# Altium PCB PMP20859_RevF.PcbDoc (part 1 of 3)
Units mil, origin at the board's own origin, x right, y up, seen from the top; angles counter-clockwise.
Board outline 5000 x 4200 mil, 4 copper layers (Top Layer, Signal Layer 1, Signal Layer 2, Bottom Layer), stack 61.2 mil thick; 264 components, 163 nets, 897 pads, 223 vias.
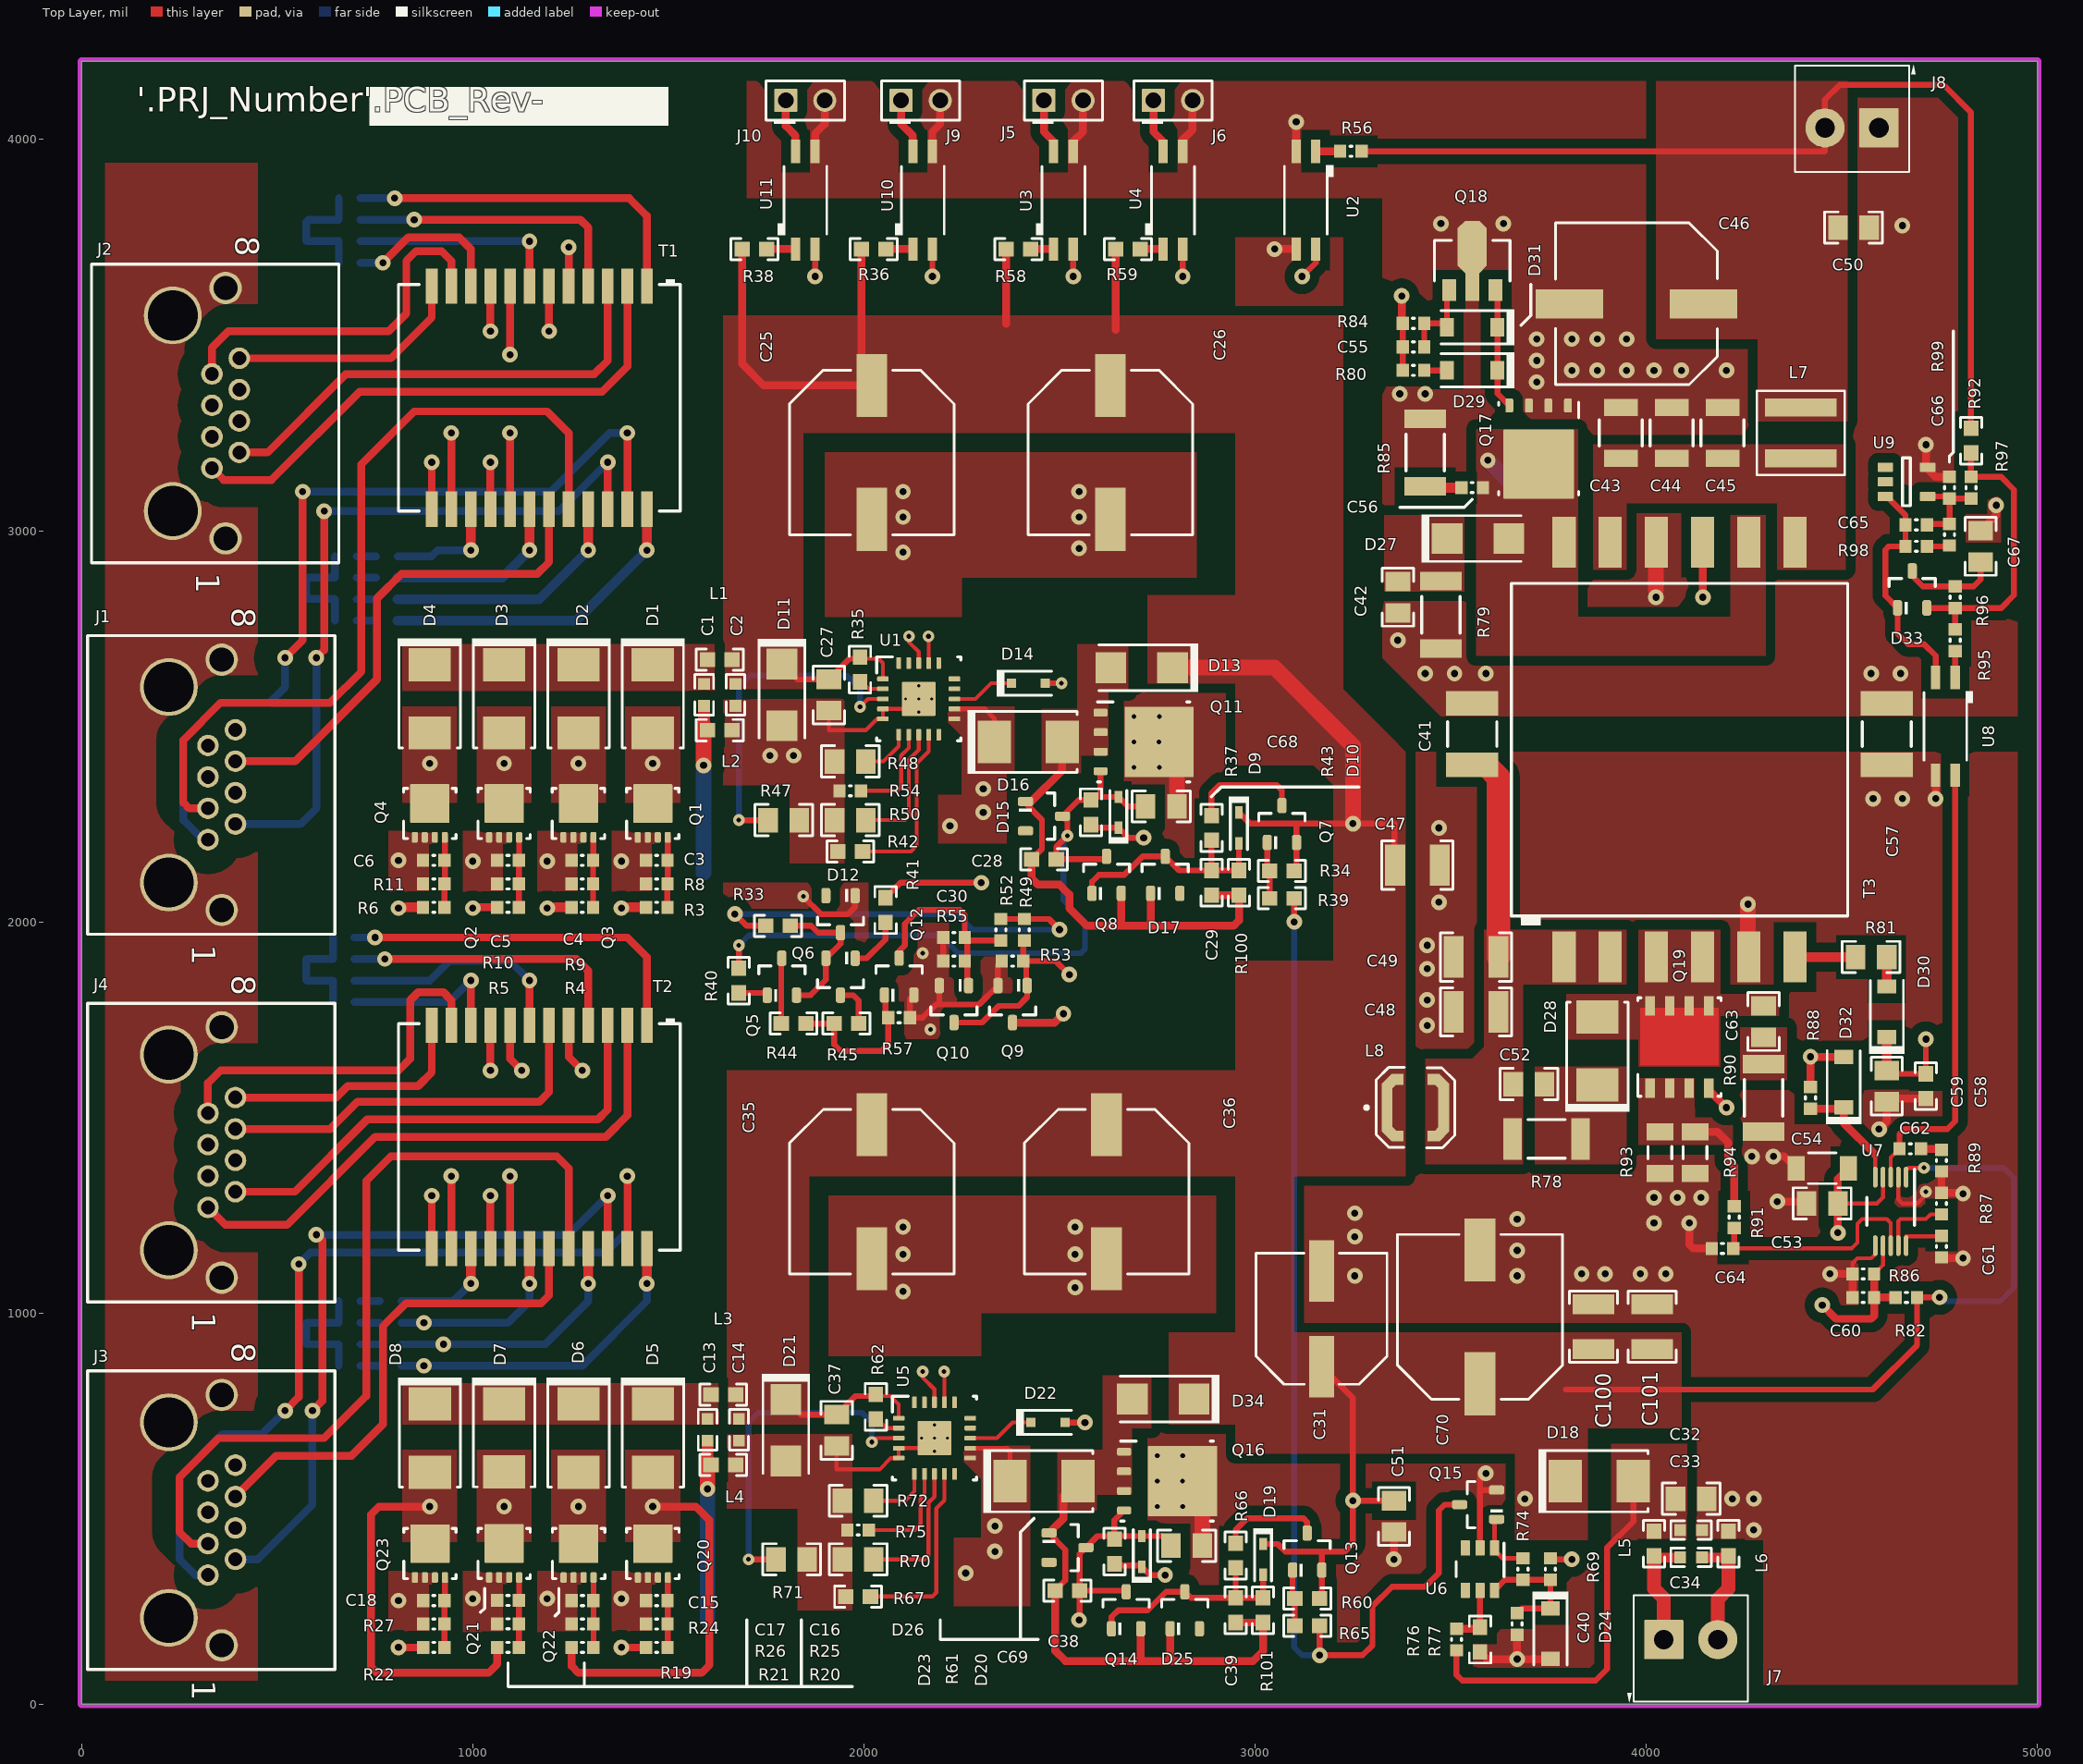
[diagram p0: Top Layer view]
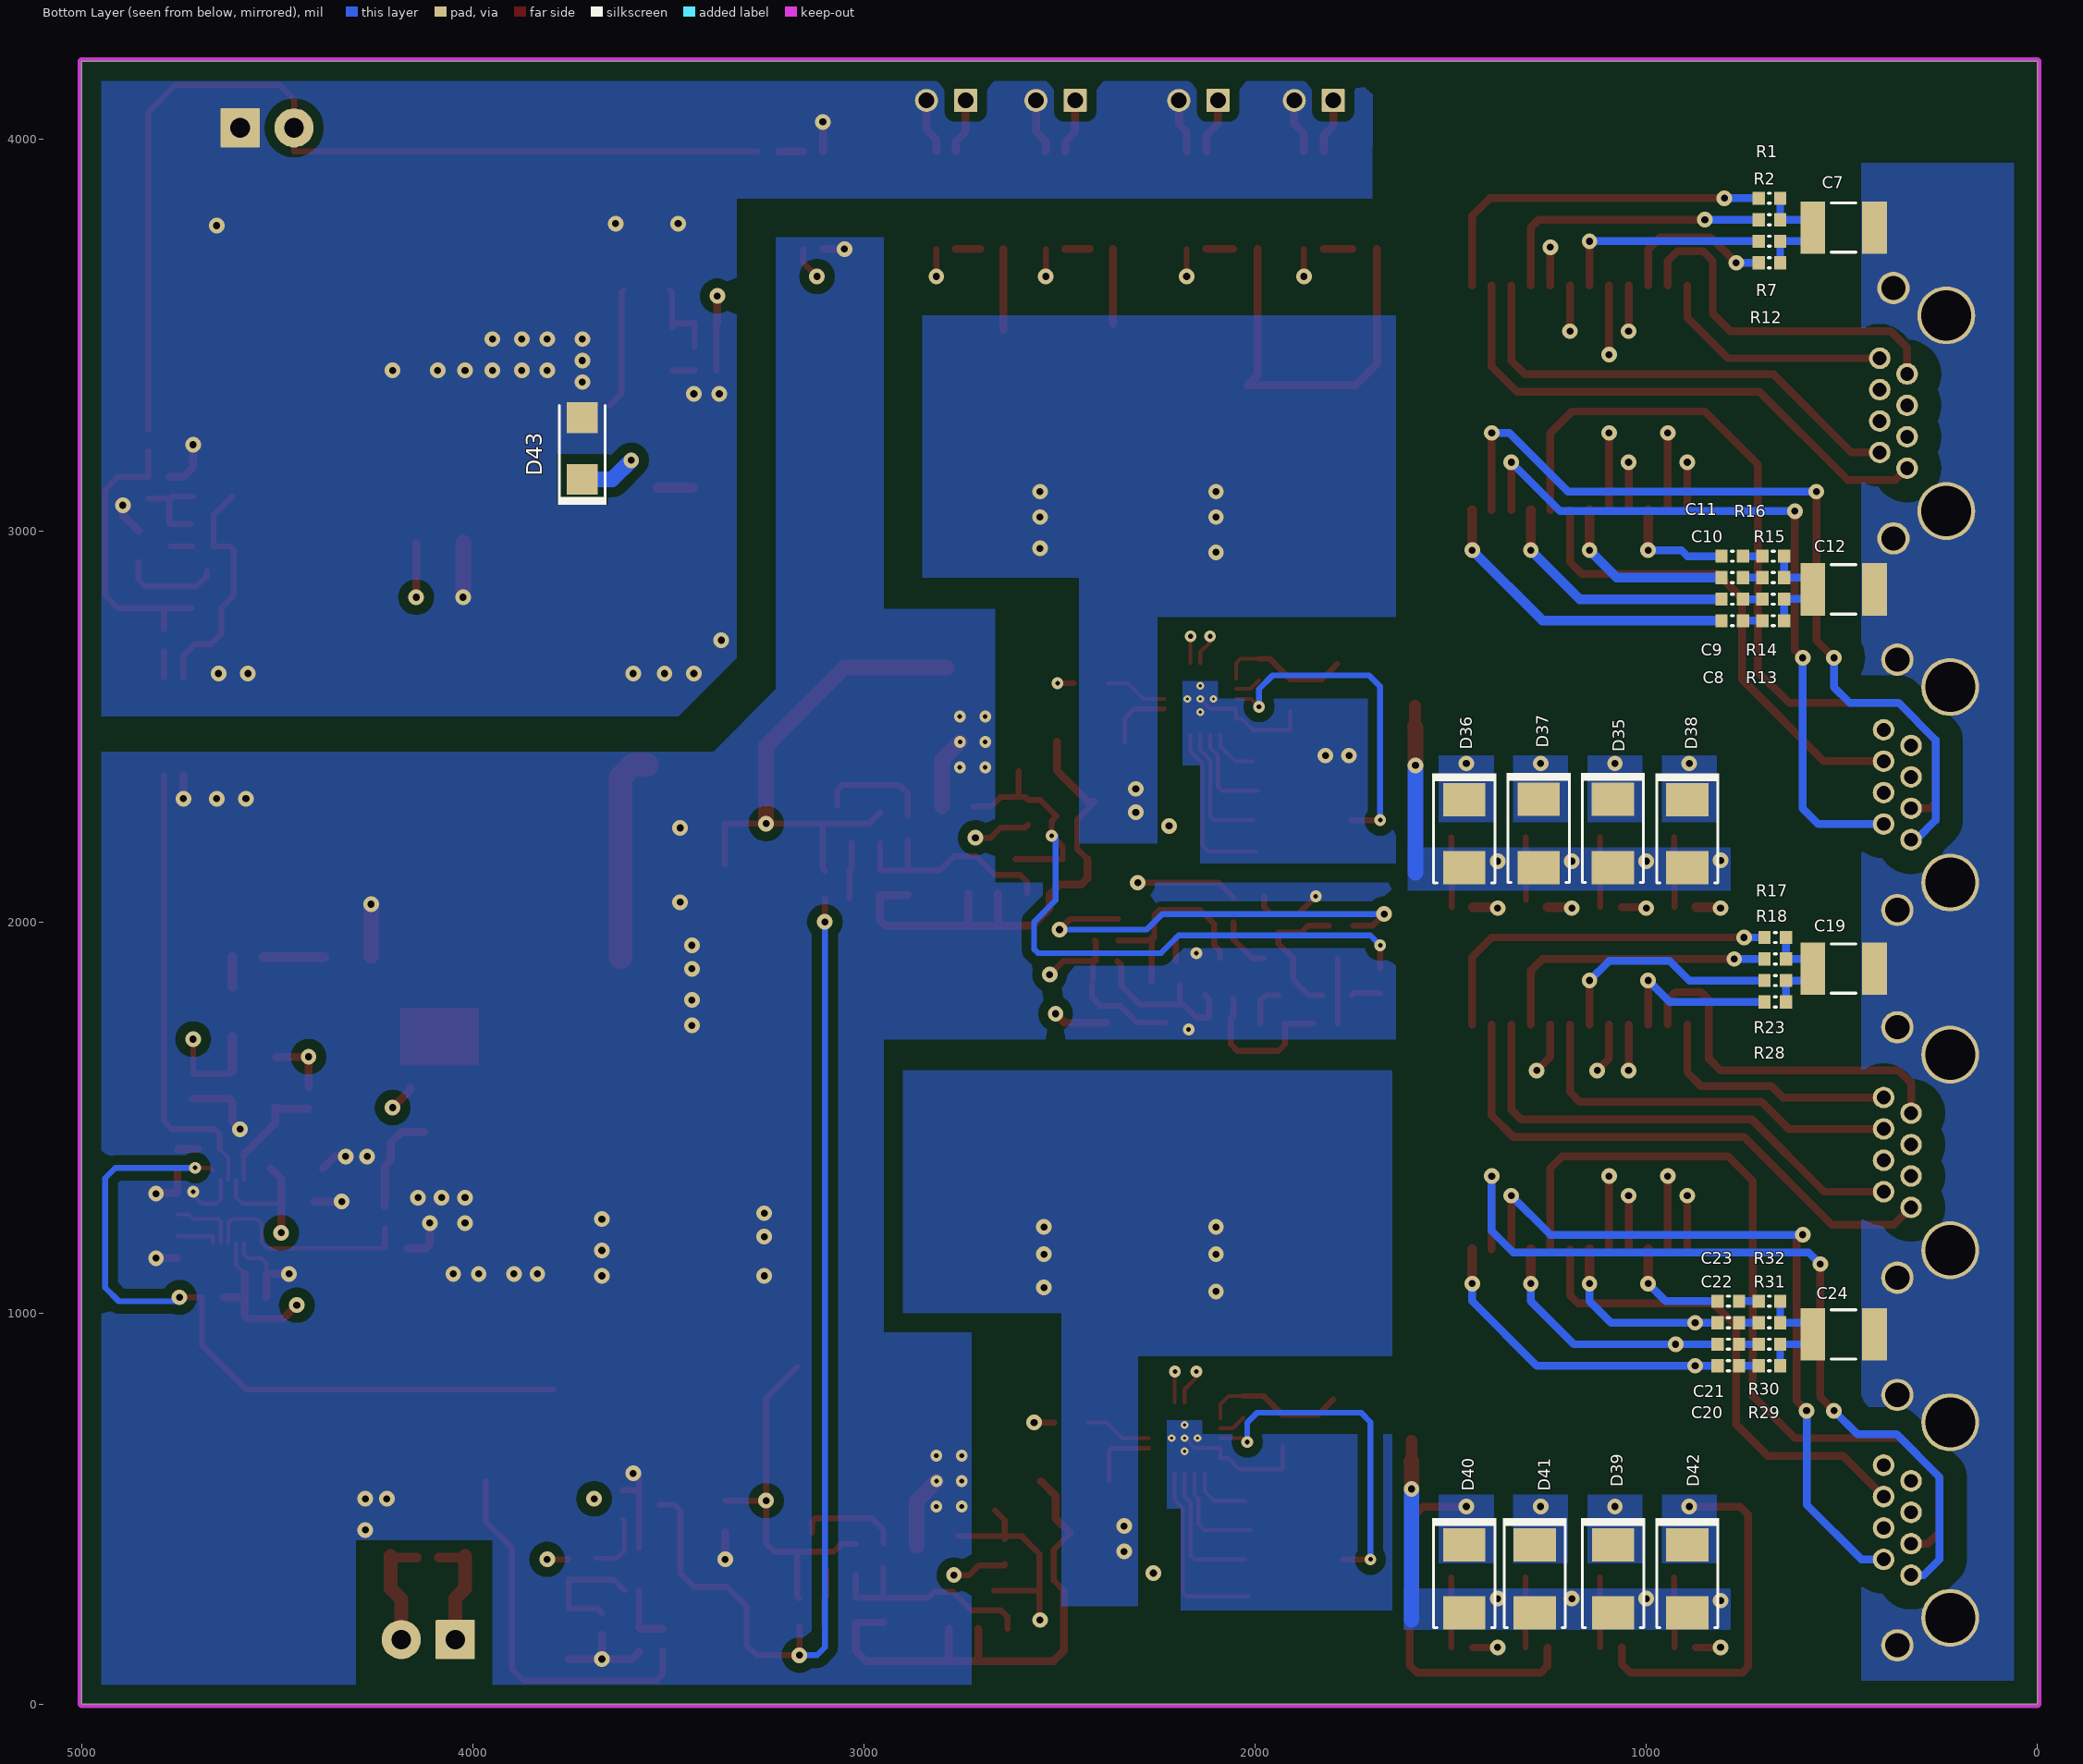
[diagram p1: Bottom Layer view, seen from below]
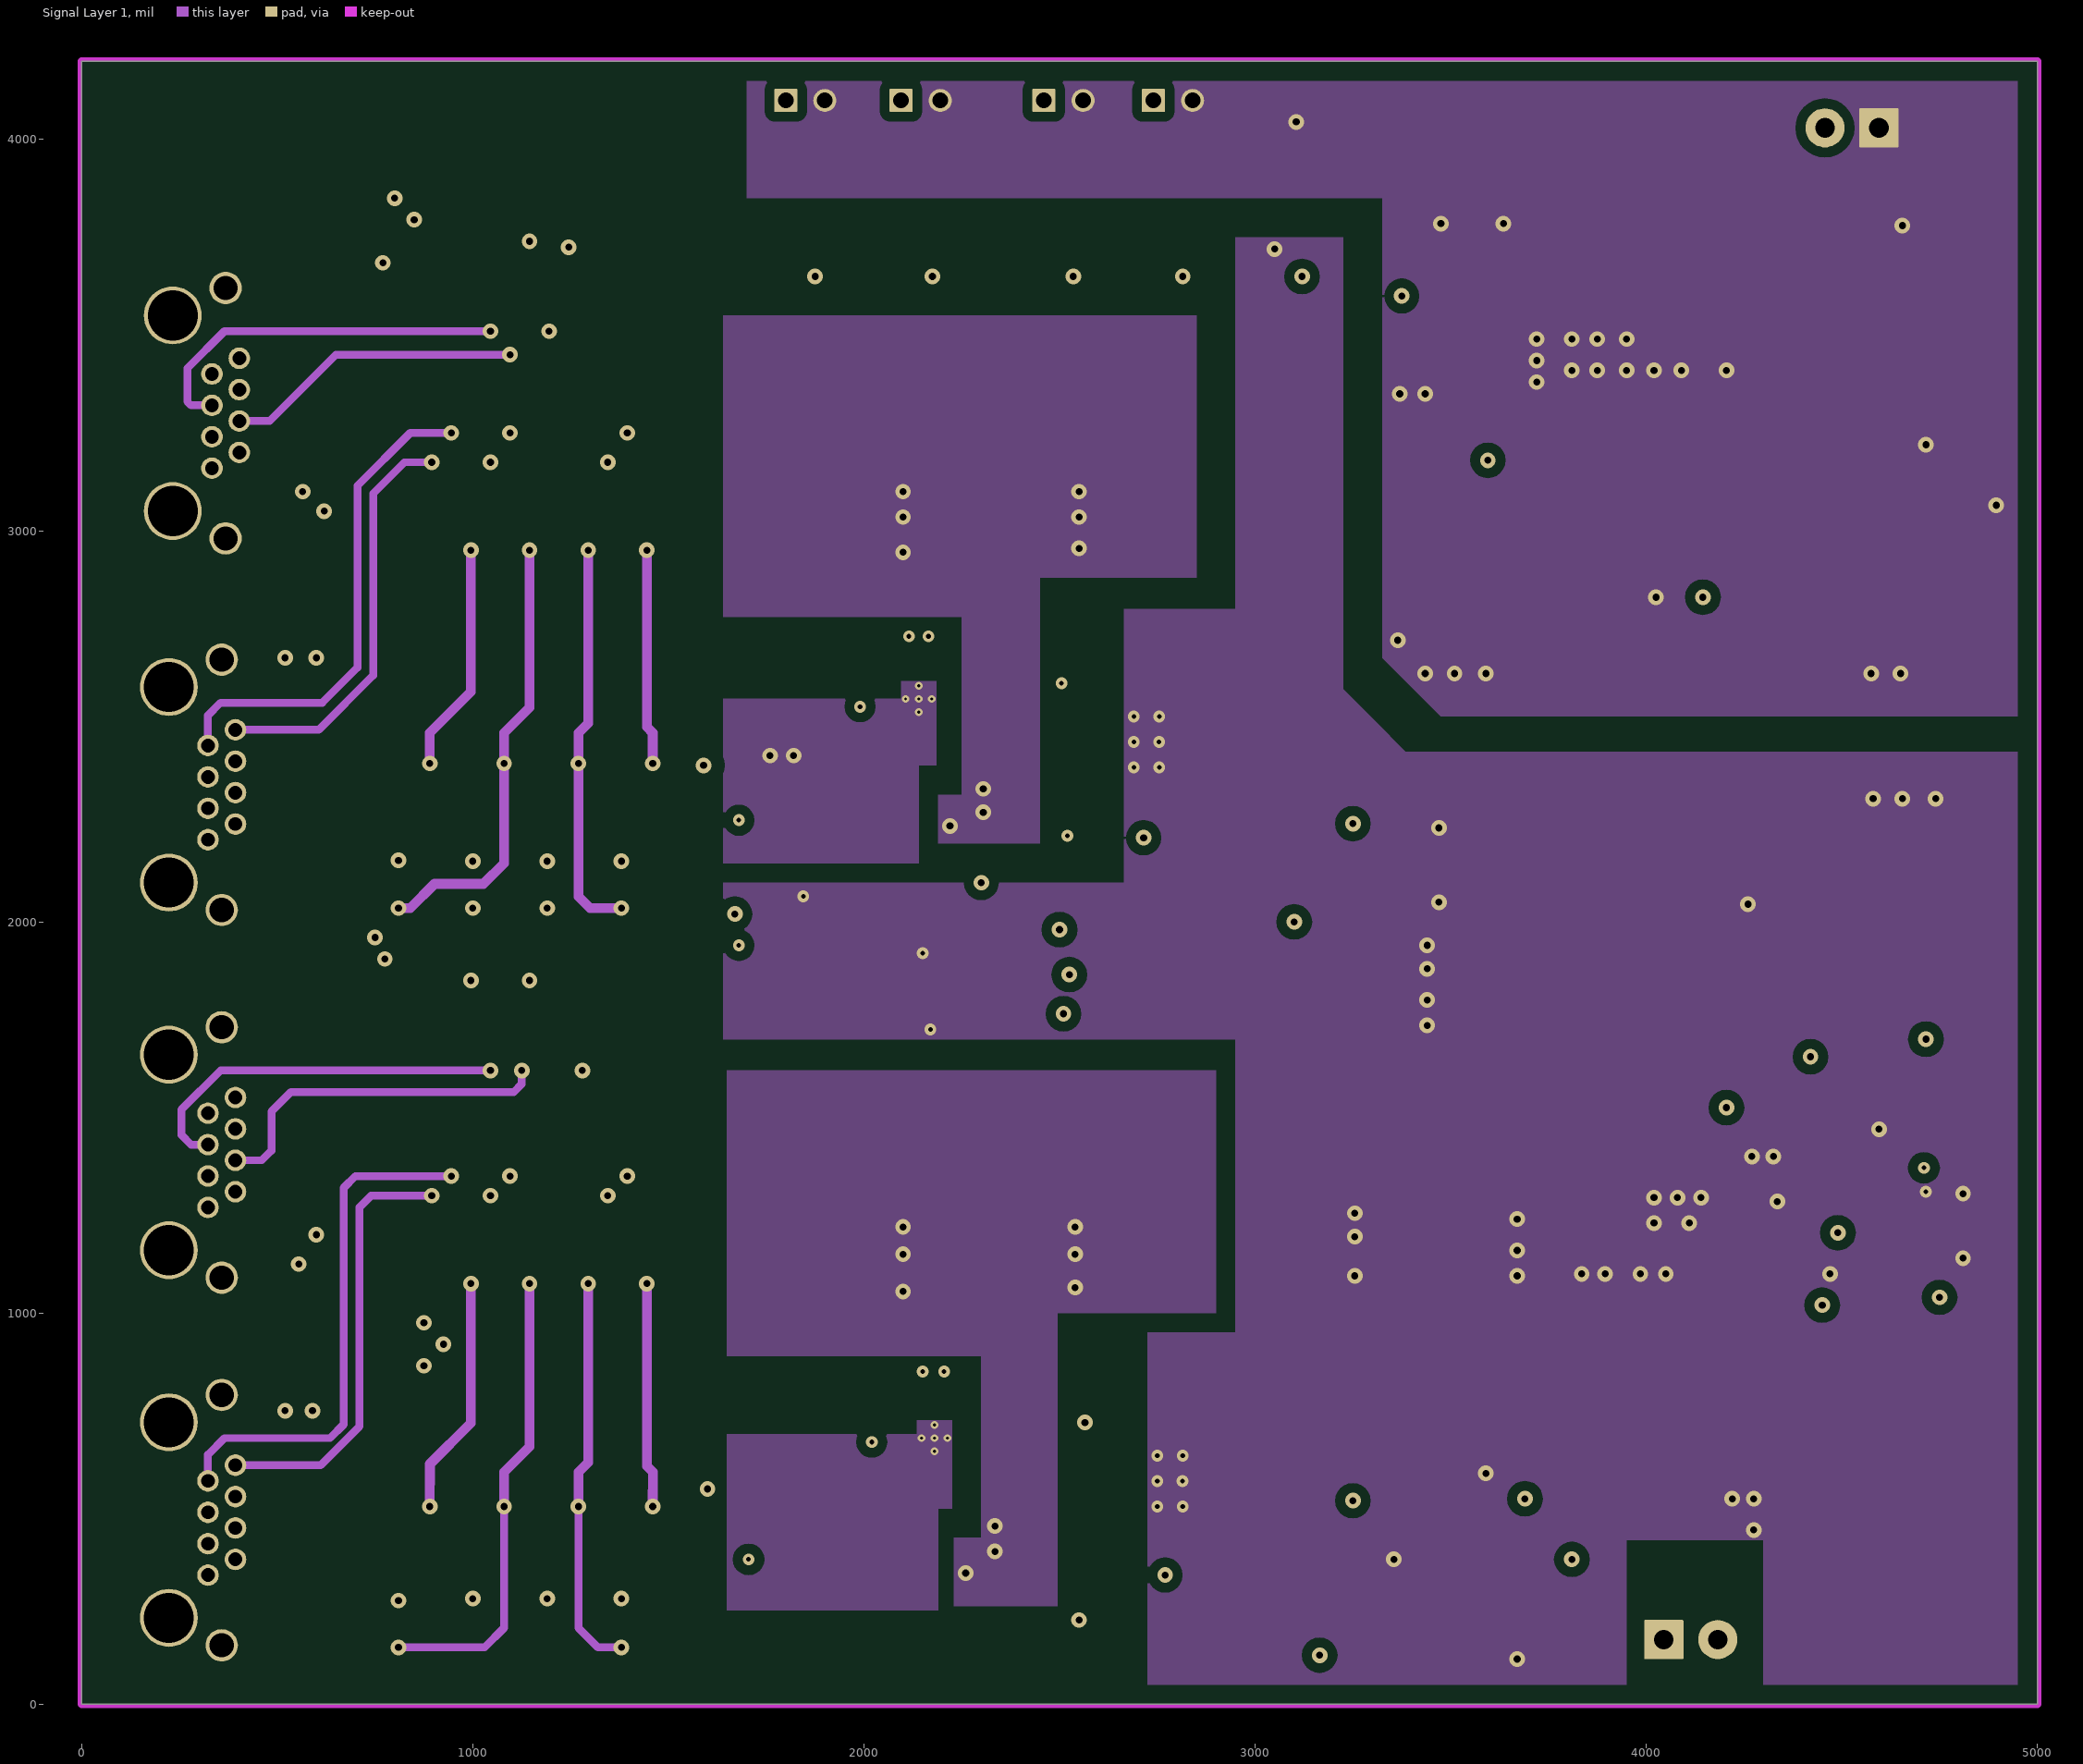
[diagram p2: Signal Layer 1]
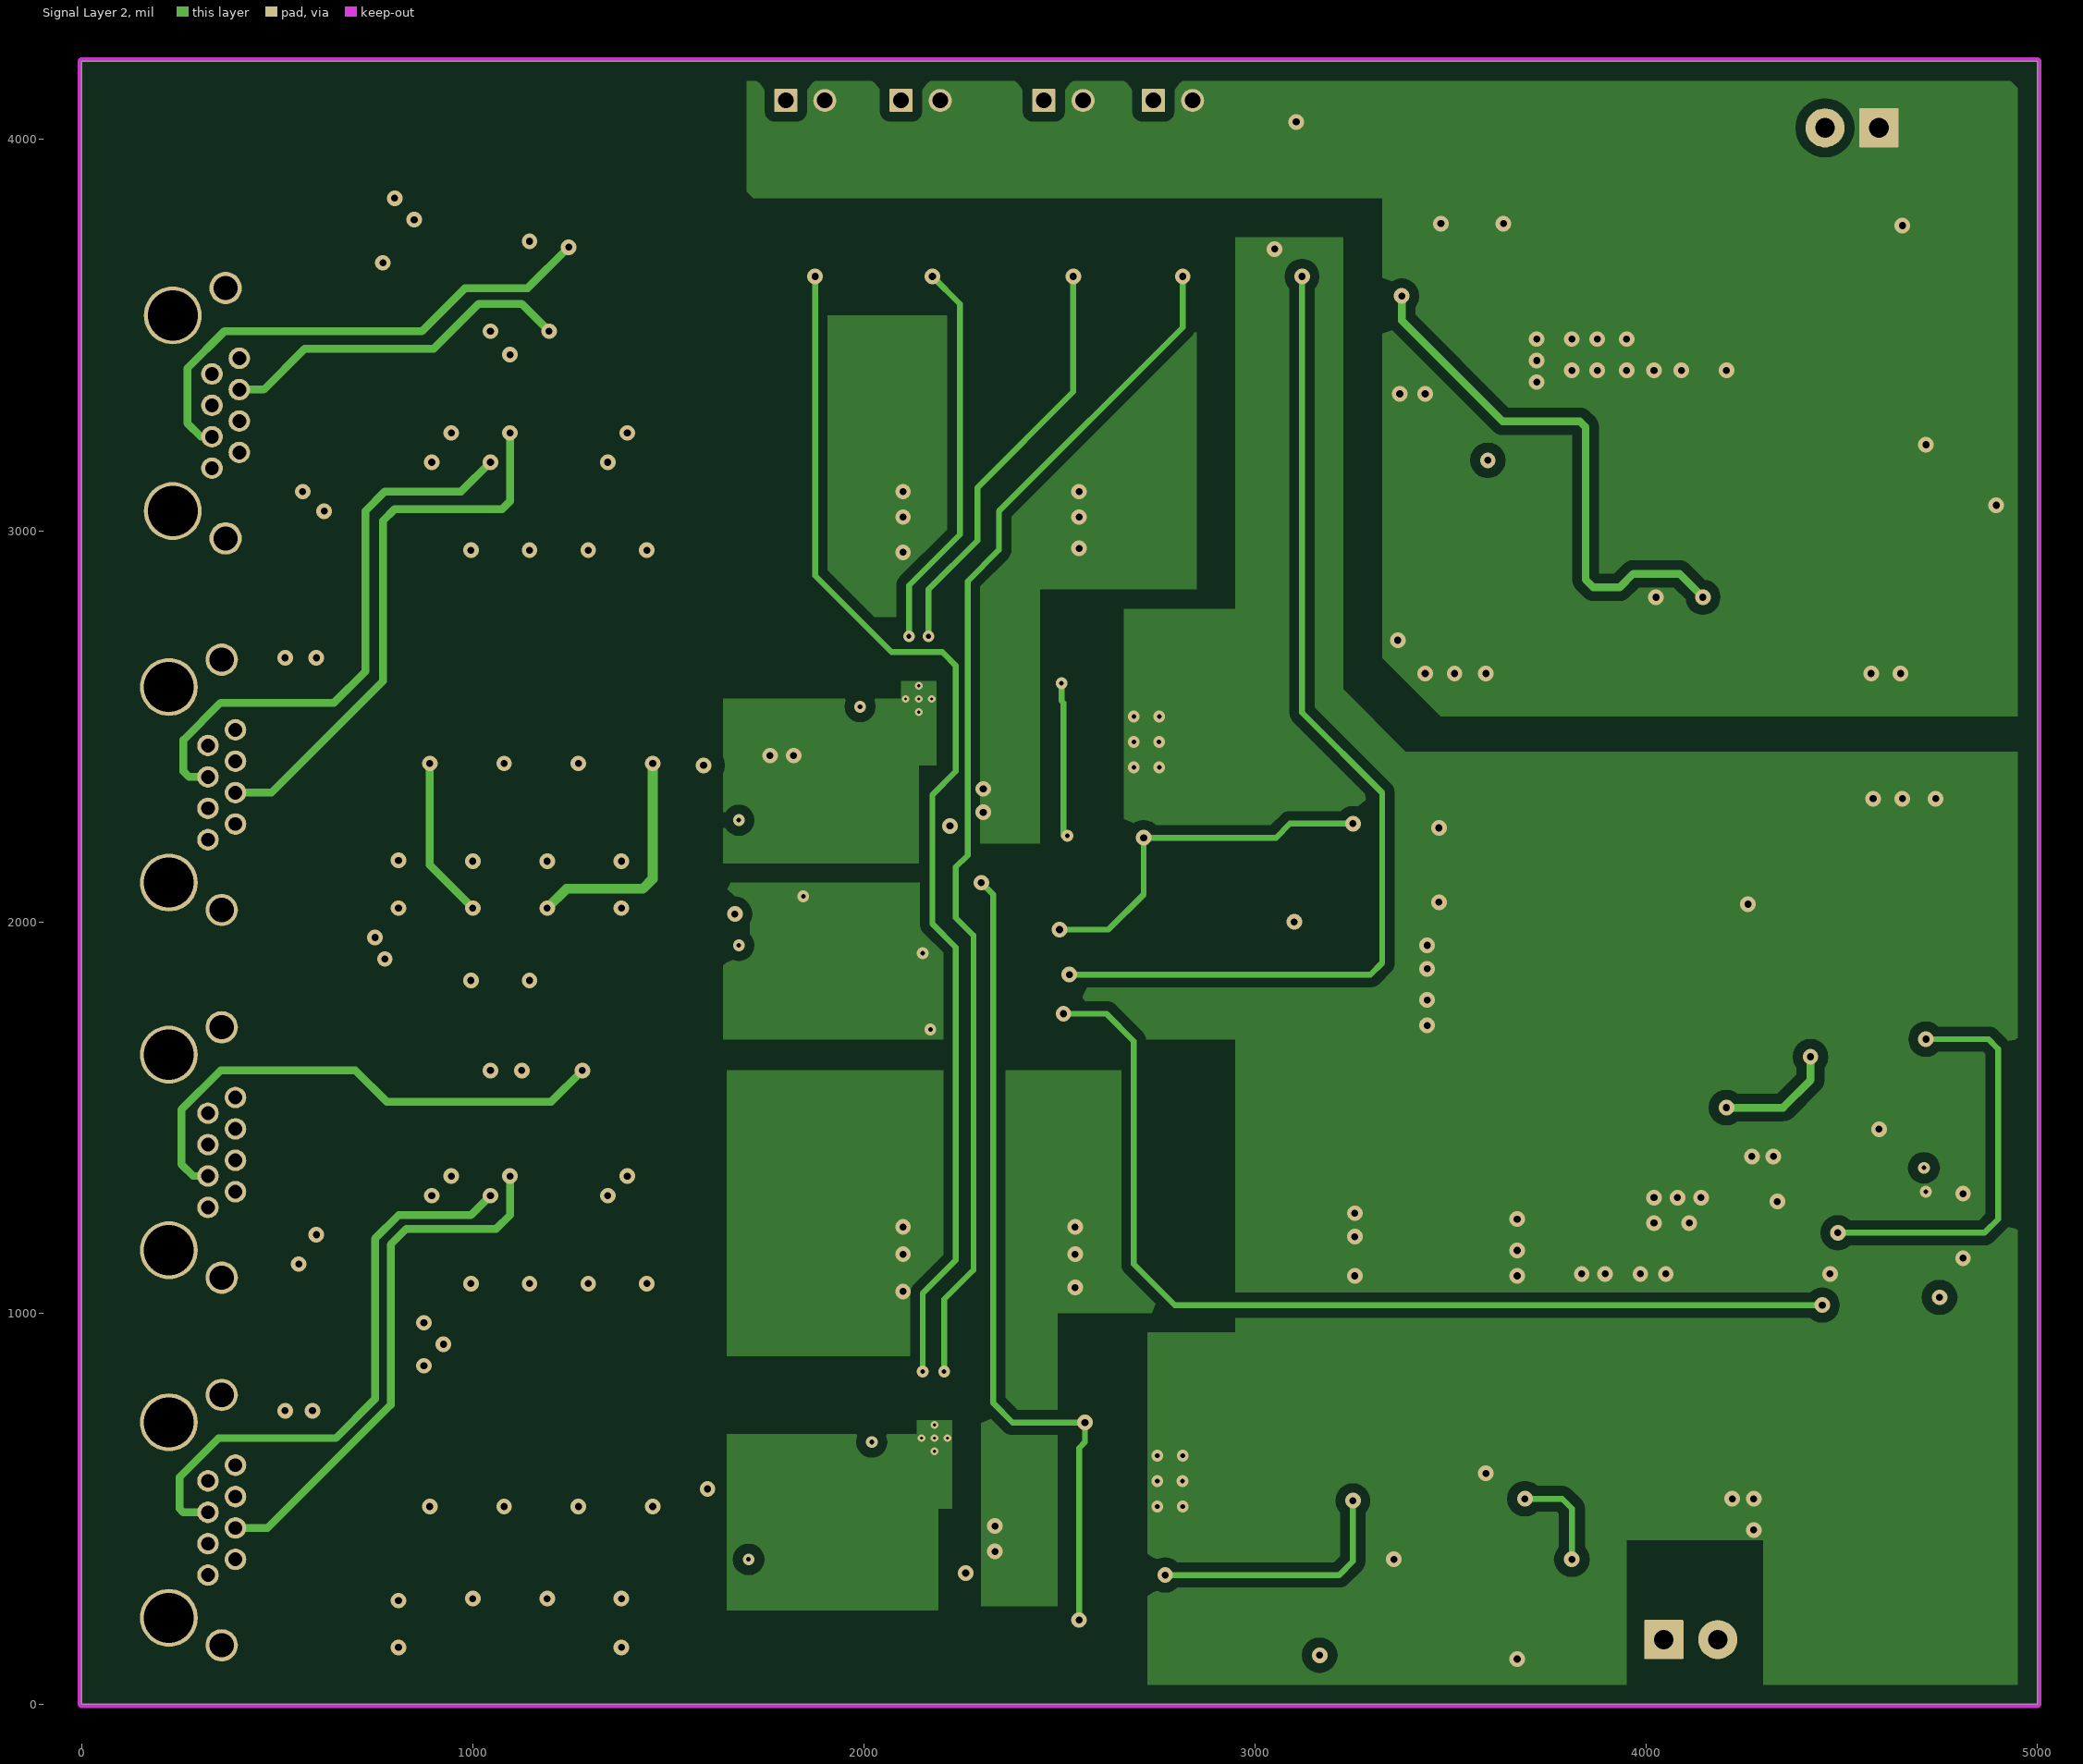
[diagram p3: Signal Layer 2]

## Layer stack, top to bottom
Top Solder: solder mask 0.4, Solder Resist, Dk 3.5
Top Layer: signal copper 2.8
Dielectric1: core 15, FR-4, Dk 4.8
Signal Layer 1: signal copper 2.8
Dielectric 2: dielectric 20, Dk 4.2
Signal Layer 2: signal copper 2.8
Dielectric 3: dielectric 15, Dk 4.2
Bottom Layer: signal copper 2.8
Bottom Solder: solder mask 0.4, Solder Resist, Dk 3.5

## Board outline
0,0 5000,0 5000,4200 0,4200

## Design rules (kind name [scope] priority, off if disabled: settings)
AcuteAngle [All] p1: minimum=4.50000000000000E+0001 checktracksonly=FALSE
AssemblyTestPointUsage [All] p1: valid=2
BoardOutlineClearance BoardOutlineClearance_MountingHoles [OnCopper and InComponentClass('Mounting Holes')] p1: gap=40 ignorepadtopadclearanceinfootprint=FALSE
BoardOutlineClearance BoardOutlineClearance_Poly [OnCopper and IsPoly] p2: gap=25 ignorepadtopadclearanceinfootprint=FALSE
BoardOutlineClearance [OnCopper and Not InComponentClass('Logo') and not InComponentClass('FiducialMark') and not InRegion(1000,500,4000,800) and not InPoly] p3: gap=50 ignorepadtopadclearanceinfootprint=FALSE
Clearance Clearance_2 [InNamedPolygon('TOP_LAYER_BSVG_P058')] p1: gap=60 ignorepadtopadclearanceinfootprint=FALSE except(0: Arc-Hole Track-Hole SMDPad-Hole THPad-Hole Via-Hole Fill-Hole Poly-Hole Region-Hole Text-Hole)
Clearance Clearance_1 [InNamedPolygon('BOTTOM_LAYER_BSVG_P057')] p2: gap=60 ignorepadtopadclearanceinfootprint=FALSE except(0: Arc-Hole Track-Hole SMDPad-Hole THPad-Hole Via-Hole Fill-Hole Poly-Hole Region-Hole Text-Hole)
Clearance Clearance_Keepouts [((IsTrack Or IsArc) And Not InPoly) And IsFree and IsKeepOut vs ((IsTrack Or IsArc) And Not InPoly) And IsFree and IsKeepOut] p3: gap=0 ignorepadtopadclearanceinfootprint=FALSE
Clearance Clearance_Poly [InPolygon] p4: gap=25 ignorepadtopadclearanceinfootprint=FALSE except(0: Arc-Hole Track-Hole SMDPad-Hole THPad-Hole Via-Hole Fill-Hole Poly-Hole Region-Hole Text-Hole)
Clearance [All] p5: gap=7.87 ignorepadtopadclearanceinfootprint=FALSE except(0: Arc-Hole Track-Hole SMDPad-Hole THPad-Hole Via-Hole Fill-Hole Poly-Hole Region-Hole Text-Hole)
ComponentClearance ComponentClearance_MountingHoles_FiducialMarks [InComponentClass('Mounting Holes') vs InComponentClass('FiducialMark')] p1: gap=50 collisioncheckmode=3 verticalgap=10 showdistances=FALSE
ComponentClearance ComponentClearance_Shunt [InComponentClass('Header') vs InComponentClass('Shunt')] p2: gap=0 collisioncheckmode=3 verticalgap=0 showdistances=FALSE
ComponentClearance ComponentClearance_Logo [InComponentClass('Logo')] p3: gap=50 collisioncheckmode=3 verticalgap=10 showdistances=FALSE
ComponentClearance ComponentClearance_ScrewToNut [(HasFootprint('NY PMS 440 0025 PH')) vs (HasFootprint('Keystone_1902C'))] p4: gap=5 collisioncheckmode=3 verticalgap=10 showdistances=FALSE
ComponentClearance ComponentClearance_MountingHoles [InComponentClass('Mounting Holes')] p5: gap=250 collisioncheckmode=3 verticalgap=100000 showdistances=FALSE
ComponentClearance ComponentClearance_SmallPassives [HasFootprint('0201*') or HasFootprint('0402*') or HasFootprint('0508') or HasFootprint('0603*') or HasFootprint('0612') or HasFootprint('0805*') or HasFootprint('0815*') or HasFootprint('0830*') or HasFootprint('1206*') or HasFootprint('1210*') or HasFootprint('1808*') or HasFootprint('1812*') or HasFootprint('1825*') or HasFootprint('2010*') or HasFootprint('2220*') or HasFootprint('2225*') or HasFootprint('2512*') or HasFootprint('2728*') or HasFootprint('3518*') vs HasFootprint('0201*') or HasFootprint('0402*') or HasFootprint('0508') or HasFootprint('0603*') or HasFootprint('0612') or HasFootprint('0805*') or HasFootprint('0815*') or HasFootprint('0830*') or HasFootprint('1206*') or HasFootprint('1210*') or HasFootprint('1808*') or HasFootprint('1812*') or HasFootprint('1825*') or HasFootprint('2010*') or HasFootprint('2220*') or HasFootprint('2225*') or HasFootprint('2512*') or HasFootprint('2728*') or HasFootprint('3518*')] p6: gap=14.96 collisioncheckmode=3 verticalgap=10 showdistances=FALSE
ComponentClearance ComponentClearance_THtoSMT [IsThruComponent vs IsSMTComponent] p7: gap=40 collisioncheckmode=3 verticalgap=30 showdistances=FALSE
ComponentClearance ComponentClearance_THtoTH [IsThruComponent vs IsThruComponent] p8: gap=30 collisioncheckmode=3 verticalgap=30 showdistances=FALSE
ComponentClearance [All] p9: gap=30 collisioncheckmode=3 verticalgap=10 showdistances=FALSE
DiffPairsRouting [All] p1: maxlimit=100 minlimit=10 mostfreqgap=10 toplayer_minwidth=15 toplayer_maxwidth=15 toplayer_prefwidth=15 midlayer1_minwidth=15 midlayer1_maxwidth=15 midlayer1_prefwidth=15 midlayer2_minwidth=15 midlayer2_maxwidth=15 midlayer2_prefwidth=15 bottomlayer_minwidth=15 bottomlayer_maxwidth=15 bottomlayer_prefwidth=15 maxuncoupledlength=1000
FabricationTestPointUsage TestPointUsage [All] p1: valid=2 allowmultiple=FALSE
FabricationTestpoint Testpoint [All] p1: side=3 testpointundercomponent=TRUE minsize=40 maxsize=100 preferedsize=60 minholesize=0 maxholesize=40 preferedholesize=32 testpointgrid=1 allowsidetop=TRUE allowsidebottom=TRUE usegrid=TRUE gridtolerance=0.01
FanoutControl Fanout_LCC [IsLCC] p1: bgadir=Out bgaviamode=Centered fanoutstyle=Auto fanoutdirection=Alternating viagrid=1 // Fanout_LCC (Default Rule)
FanoutControl Fanout_BGA [IsBGA] p2: bgadir=Out bgaviamode=Centered fanoutstyle=Auto fanoutdirection=Alternating viagrid=1 // Fanout_BGA (Default Rule)
FanoutControl Fanout_Default [All] p4: bgadir=Out bgaviamode=Centered fanoutstyle=Auto fanoutdirection=Alternating viagrid=1 // Fanout_Default (Default Rule)
FanoutControl Fanout_Small [(CompPinCount < 5)] p5: bgadir=Out bgaviamode=Centered fanoutstyle=Auto fanoutdirection=OutThenIn viagrid=1 // Fanout_Small (Default Rule)
HoleSize [All] p1: absolutevalues=TRUE maxlimit=251 minlimit=7.87 maxpercent=80.000 minpercent=20.000
MinimumAnnularRing MinimumAnnularRing_ThermalPadVias [IsVia and InAnyComponent] p1: minimumring=5.91
MinimumAnnularRing [All] p2: minimumring=8
MinimumSolderMaskSliver MinimumSolderMaskSliver_Logo [InComponentClass('Logo') vs InComponentClass('Logo')] p1: minsoldermaskwidth=0.7
MinimumSolderMaskSliver [All] p2: minsoldermaskwidth=3.94
PlaneConnect [All] p1: planeconnectstyle=Relief reliefexpansion=10 reliefentries=4 reliefconductorwidth=10 reliefairgap=10
PolygonConnect [All] p1: connectstyle=Direct reliefconductorwidth=10 reliefentries=4 polygonreliefangle="90 Angle" airgapwidth=10
RoutingVias ThermalPadVias [IsVia and InAnyComponent] p1: holewidth=7.87 width=19.68 viastyle="Through Hole" minholewidth=7.87 minwidth=19.68 maxholewidth=12.99 maxwidth=23.62
RoutingVias [All] p2: holewidth=18 width=40 viastyle="Through Hole" minholewidth=7.87 minwidth=26 maxholewidth=40 maxwidth=65
SilkToBoardRegionClearance [Not ((IsComment or IsDesignator) And (Hide <> 'False')) and not InRegion(1000,500,4000,800)] p1:
SilkToSilkClearance SilkToSilkClearance_Pb-FreeLogo [(HasFootprint('Pb-Free_Overlay_Medium') OR HasFootprint('Pb-Free_Overlay_Small')) vs (HasFootprint('Pb-Free_Overlay_Medium') OR HasFootprint('Pb-Free_Overlay_Small'))] p1: silktosilkclearance=0
SilkToSilkClearance [All] p2: silktosilkclearance=4
SilkToSolderMaskClearance SilkToComponentPadClearance [(IsPad or IsFill or IsRegion) and InAnycomponent] p1: minsilkscreentomaskgap=5 clearancetoexposedcopper=TRUE
SilkToSolderMaskClearance "Silk to Solder Mask Opening" [All] p2: minsilkscreentomaskgap=4 clearancetoexposedcopper=FALSE
SolderMaskExpansion [All] p1: expansion=1.97
Width [All] p1: maxlimit=100 minlimit=6 preferedwidth=10 checkconnectedcopper=TRUE
15 further rules are at their usual default settings.

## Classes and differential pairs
component class Header: J5 J6 J9 J10
component class PMP20859_RevF_SH1: C1 C2 C3 C4 C5 C6 C7 C8 C9 C10 C11 C12 C13 C14 C15 C16 C17 C18 C19 C20 C21 C22 C23 C24 D1 D2 D3 D4 D5 D6 D7 D8 D35 D36 D37 D38 D39 D40 D41 D42 J1 J2 J3 J4 L1 L2 L3 L4 Q1 Q2 Q3 Q4 Q20 Q21 Q22 Q23 R1 R2 R3 R4 R5 R6 R7 R8 R9 R10 R11 R12 R13 R14 R15 R16 R17 R18 R19 R20 R21 R22 R23 R24 R25 R26 R27 R28 R29 R30 R31 R32 T1 T2
component class PMP20859_RevF_SH2: C25 C26 C27 C28 C29 C30 C31 C32 C33 C34 C35 C36 C37 C38 C39 C40 C68 C69 C70 C100 C101 D9 D10 D11 D12 D13 D14 D15 D16 D17 D18 D19 D20 D21 D22 D23 D24 D25 D26 D34 J5 J6 J7 J9 J10 L5 L6 Q5 Q6 Q7 Q8 Q9 Q10 Q11 Q12 Q13 Q14 Q15 Q16 R33 R34 R35 R36 R37 R38 R39 R40 R41 R42 R43 R44 R45 R47 R48 R49 R50 R52 R53 R54 R55 R56 R57 R58 R59 R60 R61 R62 R65 R66 R67 R69 R70 R71 R72 R74 R75 R76 R77 R100 R101 U1 U2 U3 U4 U5 U6 U10 U11
component class PMP20859_RevF_SH3: C41 C42 C43 C44 C45 C46 C47 C48 C49 C50 C51 C52 C53 C54 C55 C56 C57 C58 C59 C60 C61 C62 C63 C64 C65 C66 C67 D27 D28 D29 D30 D31 D32 D33 D43 J8 L7 L8 Q17 Q18 Q19 R78 R79 R80 R81 R82 R84 R85 R86 R87 R88 R89 R90 R91 R92 R93 R94 R95 R96 R97 R98 R99 T3 U7 U8 U9

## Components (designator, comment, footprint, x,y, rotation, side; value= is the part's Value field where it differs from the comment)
C1 "Capacitor" 0603_HV 1591.32,2580 r270 top value=1000pF
C2 "Capacitor" 0603_HV 1671.32,2580 r270 top value=1000pF
C3 "Capacitor" 0603L 1470,2157.11 r180 top value=330pF
C4 "Capacitor" 0603L 1280,2157.11 r180 top value=330pF
C5 "Capacitor" 0603L 1090,2157.11 r180 top value=330pF
C6 "Capacitor" 0603L 900,2157.11 r180 top value=330pF
C7 "Capacitor" 1812 495,3775 r0 bottom value=1000pF
C8 "Capacitor" 0603L 780,2770 r180 bottom value=0.01uF
C9 "Capacitor" 0603L 780,2825 r180 bottom value=0.01uF
C10 "Capacitor" 0603L 780,2880 r180 bottom value=0.01uF
C11 "Capacitor" 0603L 780,2935 r180 bottom value=0.01uF
C12 "Capacitor" 1812 495,2850 r180 bottom value=1000pF
C13 "Capacitor" 0603_HV 1600.32,701.3 r270 top value=1000pF
C14 "Capacitor" 0603_HV 1680.32,701.3 r270 top value=1000pF
C15 "Capacitor" 0603L 1470.32,264.68 r180 top value=330pF
C16 "Capacitor" 0603L 1280.32,264.68 r180 top value=330pF
C17 "Capacitor" 0603L 1090,265 r180 top value=330pF
C18 "Capacitor" 0603L 900.32,264.68 r180 top value=330pF
C19 "Capacitor" 1812 495,1880.31 r0 bottom value=1000pF
C20 "Capacitor" 0603L 790,865 r180 bottom value=0.01uF
C21 "Capacitor" 0603L 790,920 r180 bottom value=0.01uF
C22 "Capacitor" 0603L 790,975 r180 bottom value=0.01uF
C23 "Capacitor" 0603L 790,1030 r180 bottom value=0.01uF
C24 "Capacitor" 1812 495,945 r180 bottom value=1000pF
C25 "Cap_Polarized" SM_RADIAL_G 2020,3200 r270 top value=47uF
C26 "Cap_Polarized" SM_RADIAL_G 2630,3200 r270 top value=47uF
C27 "Capacitor" 0805_HV 1910.32,2580 r90 top value=0.1uF
C28 "Capacitor" 0603 2460.32,2160 r180 top value=1000pF
C29 "Capacitor" 0603 2888.64,2100 r270 top value=1000pF
C30 "Capacitor" 0603L 2230,1959.68 r180 top value=0.01uF
C31 "Cap_Polarized" SM_RADIAL_E 3170,985 r90 top value=10uF
C32 "Capacitor" 0805_HV 4115,525 r0 top value=0.1uF
C33 "Capacitor" 0603_HV 4115,445 r0 top value=1000pF
C34 "Capacitor" 0603_HV 4115,375 r0 top value=1000pF
C35 "Cap_Polarized" SM_RADIAL_G 2020,1310 r270 top value=47uF
C36 "Cap_Polarized" SM_RADIAL_G 2620.32,1310 r270 top value=47uF
C37 "Capacitor" 0805_HV 1930.32,700 r90 top value=0.1uF
C38 "Capacitor" 0603 2520.32,290 r180 top value=1000pF
C39 "Capacitor" 0603 2950.32,240 r270 top value=1000pF
C40 "Capacitor" 0603L 3670,205 r90 top value=0.01uF
C41 "Capacitor" 1812 3555,2480 r90 top value=2200pF
C42 "Capacitor" 0805_HV 3365,2830 r90 top value=0.1uF
C43 "Capacitor" 1210_280 3935,3250 r90 top value=100uF
C44 "Capacitor" 1210_280 4065,3250 r90 top value=100uF
C45 "Capacitor" 1210_280 4195,3250 r90 top value=100uF
C46 "Cap_Polarized" SM_RADIAL_10AMM 3975,3580 r180 top value=330uF
C47 "Capacitor" 1210_270 3415,2145 r0 top value=2.2uF
C48 "Capacitor" 1210_270 3565,1770 r180 top value=2.2uF
C49 "Capacitor" 1210_270 3565,1910 r180 top value=2.2uF
C50 "Capacitor" 0805_HV 4530,3775 r0 top value=1uF
C51 "Capacitor" 0805_HV 3355,480 r270 top value=0.1uF
C52 "Capacitor" 0805_HV 3700,1585 r0 top value=0.1uF
C53 "Capacitor" 0805_HV 4450,1280 r0 top value=1uF
C54 "Capacitor" 1206_190 4450,1370 r180 top value=10uF
C55 "Capacitor" 0603L 3405,3470 r0 top value=470pF
C56 "Capacitor" 0603L 3555,3110 r0 top value=4700pF
C57 "Capacitor" 1812 4615,2480 r90 top value=2200pF
C58 "C1608X7R1E104K080AA" 0603 4715,1580 r270 top value=0.1uF
C59 "Capacitor" 0805_HV 4615,1580 r270 top value=1uF
C60 "Capacitor" 0603L 4555,1039.69 r0 top value=0.01uF
C61 "Capacitor" 0603L 4755,1169.69 r90 top value=0.01uF
C62 "Capacitor" 0603L 4675,1419.69 r180 top value=0.047uF
C63 "Capacitor" 0805_HV 4300,1745 r270 top value=100pF
C64 "Capacitor" 0603L 4195,1165 r180 top value=100pF
C65 "Capacitor" 0603L 4690.31,3015 r180 top value=1000pF
C66 "Capacitor" 0603L 4775.31,2990 r90 top value=0.068uF
C67 "Capacitor" 0805_HV 4855,2960 r90 top value=1uF
C68 "Capacitor" 0805_HV 2760,2295 r180 top value=0.047uF
C69 "Capacitor" 0805_HV 2825,405 r180 top value=0.047uF
C70 "Cap_Polarized" SM_RADIAL_G 3575,990 r90 top value=47uF
C100 "Capacitor" 1210_270 3865,965 r270 top value=2.2uF
C101 "Capacitor" 1210_270 4015,965 r270 top value=2.2uF
D1 "B2100-13-F" SMB 1460,2570 r270 top value=100V
D2 "B2100-13-F" SMB 1270,2570 r270 top value=100V
D3 "B2100-13-F" SMB 1080,2570 r270 top value=100V
D4 "B2100-13-F" SMB 890,2570 r270 top value=100V
D5 "B2100-13-F" SMB 1460.32,680 r270 top value=100V
D6 "B2100-13-F" SMB 1270.32,680 r270 top value=100V
D7 "B2100-13-F" SMB 1080,680.32 r270 top value=100V
D8 "B2100-13-F" SMB 890.32,680 r270 top value=100V
D9 "1N4148WT" Fairchild_SOD-523F 2650.32,2280 r90 top value=75V
D10 "1N4148WT" Fairchild_SOD-523F 2958.64,2240 r270 top value=75V
D11 "SMAJ58A" SMA 1790.32,2580 r270 top value=58V
D12 "MMBZ5231BLT1G" SOT-23 1940,2019.68 r270 top value=5.1V
D13 "SMAJ58A" SMA 2710,2650 r180 top value=58V
D14 "BAT46WJ,115" SOD-323F 2420.32,2610 r0 top value=100V
D15 "MMBZ5240BLT1G" SOT-23 2460.32,2270 r0 top value=10V
D16 "B2100-13-F" SMB 2420,2460 r0 top value=100V
D17 "MMBZ5240BLT1G" SOT-23 2770.32,2120 r90 top value=10V
D18 "B2100-13-F" SMB 3880,570 r0 top value=100V
D19 "1N4148WT" Fairchild_SOD-523F 3020.32,370 r270 top value=75V
D20 "1N4148WT" Fairchild_SOD-523F 2710.32,390 r90 top value=75V
D21 "SMAJ58A" SMA 1800.32,700 r270 top value=58V
D22 "BAT46WJ,115" SOD-323F 2470.32,720 r0 top value=100V
D23 "MMBZ5240BLT1G" SOT-23 2520.32,400 r0 top value=10V
D24 "MMSZ5231B-7-F" SOD-123 3755,180 r270 top value=5.1V
D25 "MMBZ5240BLT1G" SOT-23 2820.32,240 r90 top value=10V
D26 "B2100-13-F" SMB 2460.32,570 r0 top value=100V
D27 "B340A-13-F" SMA 3570,2980 r0 top value=40V
D28 "ES2D-13-F" SMB 3875,1670 r90 top value=200V
D29 "MMSD4148T1G" SOD-123 3555,3410 r180 top value=100V
D30 "MMSD4148T1G" SOD-123 4615,1770 r90 top value=100V
D31 "MMSD4148T1G" SOD-123 3555,3520 r180 top value=100V
D32 "MMSD4148T1G" SOD-123 4505,1590 r90 top value=100V
D33 "BAT54S-7-F" SOT-23 4680,2850 r90 top value=30V
D34 "SMAJ58A" SMA 2765,780 r180 top value=58V
D35 "B2100-13-F" SMB 1085.26,2225.93 r270 bottom value=100V
D36 "B2100-13-F" SMB 1465,2225 r270 bottom value=100V
D37 "B2100-13-F" SMB 1275.26,2225.93 r270 bottom value=100V
D38 "B2100-13-F" SMB 895,2225 r270 bottom value=100V
D39 "B2100-13-F" SMB 1085,320 r270 bottom value=100V
D40 "B2100-13-F" SMB 1465,320 r270 bottom value=100V
D41 "B2100-13-F" SMB 1285,320 r270 bottom value=100V
D42 "B2100-13-F" SMB 895,320 r270 bottom value=100V
D43 "SMAZ24-13-F" SMA 3720,3210 r90 bottom value=24V
J1 "1-406541-1" TEC_1-406541-1 330,2350 r270 top
J2 "1-406541-1" TEC_1-406541-1 340,3300 r270 top
J3 "1-406541-1" TEC_1-406541-1 330,470 r270 top
J4 "1-406541-1" TEC_1-406541-1 330,1410 r270 top
J5 "PEC02SAAN" CONN_PEC02SAAN 2510,4100 r0 top
J6 "PEC02SAAN" CONN_PEC02SAAN 2790,4100 r0 top
J7 "ED555/2DS" TERM_BLK_ED555-2DS 4045,165 r0 top
J8 "ED555/2DS" TERM_BLK_ED555-2DS 4595,4030 r180 top
J9 "PEC02SAAN" CONN_PEC02SAAN 2145,4100 r0 top
J10 "PEC02SAAN" CONN_PEC02SAAN 1850,4100 r0 top
L1 "Ferrite_Bead" 0603 1631.32,2670 r0 top value="220 ohm"
L2 "Ferrite_Bead" 0603 1631.32,2490 r0 top value="220 ohm"
L3 "Ferrite_Bead" 0603 1640.32,791.3 r0 top value="220 ohm"
L4 "Ferrite_Bead" 0603 1640.32,611.3 r0 top value="220 ohm"
L5 "Ferrite_Bead" 0603 4020,410 r90 top value="220 ohm"
L6 "Ferrite_Bead" 0603 4210,410 r90 top value="220 ohm"
L7 "XAL5030-331MEB" XAL5030 4395,3250 r90 top value=330nH
L8 "LPS4018-332MLB" LPS4018 3410,1525 r0 top value=3.3uH
Q1 "CSD19538Q3A" DNH0008A_NV 1460,2277.11 r90 top value=100V
Q2 "CSD19538Q3A" DNH0008A_NV 1080,2277.11 r90 top value=100V
Q3 "CSD19538Q3A" DNH0008A_NV 1270,2277.11 r90 top value=100V
Q4 "CSD19538Q3A" DNH0008A_NV 890,2277.11 r90 top value=100V
Q5 "BSS63" SOT-23 1790,1859.68 r90 top value="100 V"
Q6 "BSS63" SOT-23 1940,1859.68 r270 top value="100 V"
Q7 "BSS63" SOT-23 3068.64,2250 r90 top value="100 V"
Q8 "BSS123" SOT-23 2620.32,2120 r90 top value=100V
Q9 "BSS123" SOT-23 2380,1789.68 r270 top value=100V
Q10 "BSS123" SOT-23 2230,1789.68 r270 top value=100V
Q11 "CSD19534Q5A" DQJ0008A 2715,2460 r0 top value=100V
Q12 "BSS123" SOT-23 2090,1860 r90 top value=100V
Q13 "BSS63" SOT-23 3133.24,390 r90 top value="100 V"
Q14 "BSS123" SOT-23 2670.32,240 r90 top value=100V
Q15 "BSS123" SOT-23 3570,510 r180 top value=100V
Q16 "CSD19534Q5A" DQJ0008A 2775,570 r0 top value=100V
Q17 "CSD18504Q5A" DQJ0008A 3725,3210 r270 top value=40V
Q18 "DXT2907A-13" SOT-89-3 3555,3690 r90 top value="60 V"
Q19 "FDMS86252" TRANS_Fairchild_PQFN08A 4085,1680 r90 top value=150V
Q20 "CSD19538Q3A" DNH0008A_NV 1460.32,384.68 r90 top value=100V
Q21 "CSD19538Q3A" DNH0008A_NV 1080,385 r90 top value=100V
Q22 "CSD19538Q3A" DNH0008A_NV 1270.32,384.68 r90 top value=100V
Q23 "CSD19538Q3A" DNH0008A_NV 890.32,384.68 r90 top value=100V
R1 "Resistor" 0603L 685,3850 r0 bottom value=75.0
R2 "Resistor" 0603L 685,3795 r0 bottom value=75.0
R3 "Resistor" 0603L 1470,2037.11 r0 top value=1.00Meg
R4 "Resistor" 0603L 1280,2037.11 r0 top value=1.00Meg
R5 "Resistor" 0603L 1090,2037.11 r0 top value=1.00Meg
R6 "Resistor" 0603L 900,2037.11 r0 top value=1.00Meg
R7 "Resistor" 0603L 685,3740 r0 bottom value=75.0
R8 "Resistor" 0603L 1470,2097.11 r0 top value=232k
R9 "Resistor" 0603L 1280,2097.11 r0 top value=232k
R10 "Resistor" 0603L 1090,2097.11 r0 top value=232k
R11 "Resistor" 0603L 900,2097.11 r0 top value=232k
R12 "Resistor" 0603L 685,3685 r0 bottom value=75.0
R13 "Resistor" 0603L 675,2770 r0 bottom value=75.0
R14 "Resistor" 0603L 675,2825 r0 bottom value=75.0
R15 "Resistor" 0603L 675,2880 r0 bottom value=75.0
R16 "Resistor" 0603L 675,2935 r0 bottom value=75.0
R17 "Resistor" 0603L 670,1960 r0 bottom value=75.0
R18 "Resistor" 0603L 670,1905 r0 bottom value=75.0
R19 "Resistor" 0603L 1470.32,144.68 r0 top value=1.00Meg
R20 "Resistor" 0603L 1280.32,144.68 r0 top value=1.00Meg
R21 "Resistor" 0603L 1090,145 r0 top value=1.00Meg
R22 "Resistor" 0603L 900.32,144.68 r0 top value=1.00Meg
R23 "Resistor" 0603L 670,1850 r0 bottom value=75.0
R24 "Resistor" 0603L 1470.32,204.68 r0 top value=232k
R25 "Resistor" 0603L 1280.32,204.68 r0 top value=232k
R26 "Resistor" 0603L 1090,205 r0 top value=232k
R27 "Resistor" 0603L 900.32,204.68 r0 top value=232k
R28 "Resistor" 0603L 670,1795 r0 bottom value=75.0
R29 "Resistor" 0603L 685,865 r0 bottom value=75.0
R30 "Resistor" 0603L 685,920 r0 bottom value=75.0
R31 "Resistor" 0603L 685,975 r0 bottom value=75.0
R32 "Resistor" 0603L 685,1030 r0 bottom value=75.0
R33 "Resistor" 0603 1780,1990 r180 top value=20.0k
R34 "Resistor" 0603 3068.64,2130 r0 top value=10.0k
R35 "Resistor" 0603 1990,2645 r90 top value=27.4k
R36 "RC0603FR-0735K7L" 0603 2025,3720 r0 top value=35.7k
R37 "Resistor" 0603 2580.32,2280 r270 top value=100k
R38 "RC0603FR-0735K7L" 0603 1720,3720 r0 top value=35.7k
R39 "Resistor" 0603 3068.64,2060 r0 top value=137k
R40 "Resistor" 0603 1680,1849.68 r270 top value=100k
R41 "Resistor" 0603 2055,2030 r270 top value=100k
R42 "CRCW060360K4FKEA" 0603 1965,2180 r180 top value=60.4k
R43 "Resistor" 0603 2888.64,2240 r90 top value=100k
R44 "Resistor" 0603 1820,1740 r0 top value=1.78k
R45 "Resistor" 0603 1955,1740 r0 top value=1.78k
R47 "Resistor" 0805_HV 1795,2260 r180 top value=63.4
R48 "CRCW08051K21FKEA" 0805_HV 1965,2410 r0 top value=1.21k
R49 "Resistor" 0603L 2410,1979.68 r90 top value=44.2k
R50 "Resistor" 0805_HV 1965,2260 r180 top value=1.3k
R52 "Resistor" 0603L 2350,1979.68 r270 top value=44.2k
R53 "Resistor" 0603L 2380,1899.68 r0 top value=10.0k
R54 "Resistor" 0603L 1965,2335 r0 top value=49.9k
R55 "Resistor" 0603L 2230,1899.68 r0 top value=10.0k
R56 "Resistor" 0603L 3245,3970 r0 top value=1.00k
R57 "Resistor" 0603L 2090,1755 r180 top value=10.0k
R58 "RC0603FR-0735K7L" 0603 2395,3720 r0 top value=35.7k
R59 "RC0603FR-0735K7L" 0603 2675,3720 r0 top value=35.7k
R60 "CRCW060310K0FKEA" 0603 3133.24,270 r0 top value=10.0k
R61 "Resistor" 0603 2640.32,390 r270 top value=100k
R62 "Resistor" 0603 2030.32,760 r90 top value=27.4k
R65 "Resistor" 0603 3133.24,200 r0 top value=137k
R66 "Resistor" 0603 2950.32,380 r90 top value=100k
R67 "CRCW060360K4FKEA" 0603 1985,275 r180 top value=60.4k
R69 "Resistor" 0603L 3755,345 r90 top value=10.0k
R70 "Resistor" 0805_HV 1985,370 r180 top value=1.3k
R71 "Resistor" 0805_HV 1815,370 r180 top value=63.4
R72 "CRCW08051K21FKEA" 0805_HV 1985,520 r0 top value=1.21k
R74 "Resistor" 0603L 3685,345 r90 top value=20.0k
R75 "Resistor" 0603L 1985,445 r0 top value=49.9k
R76 "Resistor" 0603L 3515,165 r270 top value=100k
R77 "Resistor" 0603 3575,165 r90 top value=1.02k
R78 "Resistor" 2010L 3745,1445 r180 top value=30k
R79 "Resistor" 2010L 3475,2785 r270 top value=2.0k
R80 "Resistor" 0603L 3405,3410 r180 top value=4.7
R81 "Resistor" 0805_HV 4575,1910 r180 top value=20
R82 "Resistor" 0603L 4665,1039.69 r0 top value=100k
R84 "Resistor" 0603L 3405,3530 r180 top value=4.99k
R85 "Resistor" 2010L 3435,3200 r270 top value=3.3
R86 "Resistor" 0603L 4555,1099.69 r0 top value=3.83k
R87 "Resistor" 0603L 4755,1279.69 r270 top value=25.5k
R88 "Resistor" 0603L 4420,1550 r270 top value=49.9
R89 "Resistor" 0603L 4755,1389.69 r90 top value=750
R90 "Resistor" 2010L 4300,1550 r90 top value=75
R91 "Resistor" 0603L 4225,1245 r90 top value=332
R92 "Resistor" 0603 4830.31,3230 r270 top value=0
R93 "Resistor" 1206L 4035,1410 r90 top value=0.27
R94 "Resistor" 1206L 4125,1410 r90 top value=0.27
R95 "Resistor" 0603L 4790,2720 r90 top value=665
R96 "Resistor" 0603L 4790,2830 r270 top value=10.0k
R97 "Resistor" 0603L 4830.31,3110 r270 top value=10.0k
R98 "Resistor" 0603L 4690.31,2960 r180 top value=1.00k
R99 "Resistor" 0603L 4775.31,3110 r270 top value=3.24k
R100 "Resistor" 0603 2958.64,2100 r90 top value=30.1k
R101 "Resistor" 0603 3020.32,240 r90 top value=30.1k
T1 "7490220122" Wurth_7490220122 1170,3340 r270 top value=350uH
T2 "7490220122" Wurth_7490220122 1170,1450 r270 top value=350uH
T3 "PA4577NL" Pulse_PA4577NL 4085,2440 r90 top value=35uH
U1 "TPS2372-3RGWR" RGW0020B 2140,2570 r0 top
U2 "HMHA2801A" MFP04A 3130,3845 r270 top
U3 "HMHA2801A" MFP04A 2510,3845 r90 top
U4 "HMHA2801A" MFP04A 2790,3845 r90 top
U5 "TPS2372-3RGWR" RGW0020B 2180.32,680 r0 top
U6 "TPS3808G01DBVR" DBV0006A_N 3575,345 r270 top
U7 "LM5020MM-1/NOPB" DGS0010A_N 4625,1259.69 r270 top
U8 "HMHA2801A" MFP04A 4765,2500 r270 top
U9 "TLV431AIDBVR" DBV0005A_N 4665.31,3125 r0 top
U10 "HMHA2801A" MFP04A 2150,3845 r90 top
U11 "HMHA2801A" MFP04A 1850,3845 r90 top

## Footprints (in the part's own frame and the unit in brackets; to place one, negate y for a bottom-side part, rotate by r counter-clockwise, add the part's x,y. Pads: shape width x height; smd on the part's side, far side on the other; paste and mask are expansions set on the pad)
0603 [mm] "0603 from SM-752 data"
  rect 1x0.95 smd: 1(-0.8,0) 2(0.8,0)
  silkscreen extent -1.52,-0.69 1.52,0.69, body extent -0.87,-0.47 0.87,0.47, height 1
0603_HV [mil] "Ernesto recommended land pattern.  26 mil between pads."
  rect 30x30 smd: 1(-28,0) 2(28,0)
  silkscreen extent -52,-24 52,24, body extent -34,-19 34,19, height 39
0603L [mm] "0603 from SM-752 data"
  rect 0.8x0.85 smd: 1(-0.7,0) 2(0.7,0)
  silkscreen extent -0.07,-0.33 0.07,0.33, body extent -0.87,-0.47 0.87,0.47, height 1
0805_HV [mil] "0805 with 30mil clearance between pads"
  rect 50x63 smd: 1(-40,0) 2(40,0)
  silkscreen extent -74,-40 74,40, body extent -43,-29 43,29, height 57
1206_190 [mm] "1206_190"
  rect 1.1x1.6 smd: 1(-1.7,0) 2(1.7,0)
  silkscreen extent -0.9,-1 0.9,1, body extent -1.75,-0.95 1.75,0.95, height 1.9
1206L [mm] "1206 from SM-752 data"
  rect 1.1x1.75 smd: 1(-1.35,0) 2(1.35,0)
  silkscreen extent -0.4,-0.77 0.4,0.77, body extent -1.7,-0.9 1.7,0.9, height 1.35
1210_270 [mm] "1210"
  rect 1.3x2.7 smd: 1(-1.45,0) 2(1.45,0)
  silkscreen extent -2.32,-1.57 2.32,1.57, body extent -1.7,-1.35 1.7,1.35, height 2.7
1210_280 [mm] "SMD, 2-Leads, Body 3.6x2.8mm, Height 2.8mm"
  rect 1.1x2.2 smd: 1(-1.65,0) 2(1.65,0)
  silkscreen extent -0.84,-1.4 0.84,1.4, body extent -1.8,-1.4 1.8,1.4, height 2.8
1812 [mm]
  rect 1.6x3.4 smd: 1(-2,0) 2(2,0)
  silkscreen extent -0.8,-1.6 0.8,1.6, body extent -2.4,-1.7 2.4,1.7, height 1.35
2010L [mm]
  rect 1.2x2.7 smd: 1(-2.2,0) 2(2.2,0)
  silkscreen extent -1.2,-1.25 1.2,1.25, body extent -2.73,-1.45 2.73,1.45, height 1.66
CONN_PEC02SAAN [mm] "SULLINS"
  rrect7% 1.5x1.5 hole 1.016: 1(-1.27,0)
  round 1.5 hole 1.016: 2(1.27,0)
  silkscreen extent -2.54,-1.52 2.54,1.27, body extent -2.54,-1.27 2.54,1.27, height 8.38
DBV0005A_N [mm] "SOT23, 5-Leads, Body 2.9x1.6mm, Pitch 0.95mm, Lead Span 2.8mm, IPC Medium Density"
  rrect17% 1x0.6 smd: 1(-1.375,0.95) 2(-1.375,0) 3(-1.375,-0.95) 4(1.375,-0.95) 5(1.375,0.95)
  silkscreen extent -0.25,-1.55 0.25,1.55, body extent -1.42,-1.46 1.42,1.46, height 1.09
DBV0006A_N [mm] "SOT23, 6-Leads, Body 2.9x1.6mm, Pitch 0.95mm, Lead Span 2.8mm, IPC Medium Density"
  rrect17% 1x0.6 smd: 1(-1.375,0.95) 2(-1.375,0) 3(-1.375,-0.95) 4(1.375,-0.95) 5(1.375,0) 6(1.375,0.95)
  silkscreen extent -1.68,-1.55 0.5,1.55, body extent -1.42,-1.46 1.42,1.46, height 1.12
DGS0010A_N [mm] "TSSOP, 10-Leads, Body 3x3mm, Pitch 0.5mm, IPC Medium Density"
  oval 1.35x0.3 smd: 1(-2.225,1) 2(-2.225,0.5) 3(-2.225,0) 4(-2.225,-0.5) 5(-2.225,-1) 6(2.225,-1) 7(2.225,-0.5) 8(2.225,0) 9(2.225,0.5) 10(2.225,1)
  silkscreen extent -2.75,-1.55 0.9,1.55, body extent -2.45,-1.5 2.45,1.5, height 0.96
DNH0008A_NV [mm] "8 pin VSONP, 0.65 mm pitch"
  rrect50% 0.7x0.4 smd paste-0.05 mask-0.05: 1(-1.55,0.975) 2(-1.55,0.325) 3(-1.55,-0.325) 4(-1.55,-0.975) 5(1.55,-0.975) 6(1.55,-0.325) 7(1.55,0.325) 8(1.55,0.975)
  rrect14% 0.705x1.125 on Top Paste: 9(-0.208,0.662) 9(-0.208,-0.663) 9(0.697,-0.663) 9(0.697,0.662)
  rrect6% 1.775x2.45 on Top Solder: 9(0.327,0)
  rrect4% 2.51x2.55 smd paste-1.5 mask-1.5: 9(0.645,0)
  rect 0.5x0.3 on Top Solder: 9(1.175,-0.975) 9(1.175,-0.325) 9(1.175,0.325) 9(1.175,0.975)
  silkscreen extent -1.62,-1.7 1.62,1.7, body extent -1.65,-1.65 1.65,1.66, height 0.91
DQJ0008A [mm] "SMD, 8-Leads, Body 5.75x4.9mm"
  rrect39% 0.91x0.51 smd paste-0.05 mask-0.05: 1(-2.795,1.905) 2(-2.795,0.635) 3(-2.795,-0.635) 4(-2.795,-1.905) 5(2.795,-1.905) 6(2.795,-0.635) 7(2.795,0.635) 8(2.795,1.905)
  rrect8% 1.58x1.25 on Top Paste: 9(-0.38,-1.45) 9(-0.38,0) 9(-0.38,1.45) 9(1.4,-1.45) 9(1.4,0) 9(1.4,1.45)
  rrect3% 3.48x4.47 on Top Solder: 9(0.55,0)
  rrect2% 4.49x4.57 smd paste-2.5 mask-2.5: 9(1.005,0)
  silkscreen extent -3,-2.6 3,2.6, body extent -3.13,-2.45 3.13,2.45, height 1.15
Fairchild_SOD-523F [mm] "SMD, 2-Leads, Body 1.2x0.8mm"
  rect 0.8x0.5 smd: 1(-1,0) 2(1,0)
  silkscreen extent -2.03,-0.65 1.4,0.65, body extent -0.65,-0.45 0.65,0.45, height 0.7
LPS4018 [mil]
  rect 28x123 smd: 1(-72.5,0) 2(72.5,0)
  rect 35.5x28 smd rot 135: 1(-64,-64) 2(64,64)
  rect 35.5x28 smd rot 45: 1(-64,64) 2(64.5,-63.5)
  rect 31.5x28 smd: 1(-46,-72.5) 1(-46,72.5) 2(46,-72.5) 2(46,72.5)
  silkscreen extent -129,-102 100,102, body extent -81,-81 81,81, height 71
MFP04A [mm] "FAIRCHILD optocoupler"
  rect 1.52x0.61 smd: 1(-3.175,0.635) 2(-3.175,-0.635) 3(3.175,-0.635) 4(3.175,0.635)
  silkscreen extent -2.28,-1.4 2.2,1.8, body extent -3.6,-1.34 3.6,1.34, height 2.39
Pulse_PA4577NL [mm] "SMT, 12-Leads, Body 21.84x21.6mm, Pitch 3mm"
  rect 3.305x1.52 smd: 1(-13.463,7.5) 2(-13.463,4.5) 3(-13.463,1.5) 4(-13.463,-1.5) 5(-13.463,-4.5) 6(-13.463,-7.5) 7(13.463,-7.5) 8(13.463,-4.5) 9(13.463,-1.5) 10(13.463,1.5) 11(13.463,4.5) 12(13.463,7.5)
  silkscreen extent -11.4,-10.92 10.8,10.92, body extent -14.6,-10.92 14.6,10.92, height 11.43
RGW0020B [mm] "QFN, 20-Leads, Body 5x5mm, Pitch 0.65mm, Thermal Pad 2.2x2.2mm, TI Recommended"
  rrect32% 0.75x0.31 smd: 1(-2.325,1.3) 2(-2.325,0.65) 3(-2.325,0) 4(-2.325,-0.65) 5(-2.325,-1.3) 11(2.325,-1.3) 12(2.325,-0.65) 13(2.325,0) 14(2.325,0.65) 15(2.325,1.3)
  rrect32% 0.31x0.75 smd: 6(-1.3,-2.325) 7(-0.65,-2.325) 8(0,-2.325) 9(0.65,-2.325) 10(1.3,-2.325) 16(1.3,2.325) 17(0.65,2.325) 18(0,2.325) 19(-0.65,2.325) 20(-1.3,2.325)
  rrect10% 0.98x0.98 on Top Paste: 21(-0.59,-0.59) 21(-0.59,0.59) 21(0.59,-0.59) 21(0.59,0.59)
  rrect5% 2.2x2.2 smd paste-1.1: 21(0,0)
  silkscreen extent -2.73,-2.73 2.73,2.73, body extent -2.5,-2.5 2.5,2.5, height 0.97
SM_RADIAL_10AMM [mm] "10 x 7.9mm:  Sanyo Oscon F8"
  rect 4.4x1.9 smd: 1(-4.35,0) 2(4.35,0)
  silkscreen extent -5.25,-5.25 5.25,5.25, body extent -5.25,-5.25 5.25,5.25, height 8
SM_RADIAL_E [mm] "8 x 6.2mm:  Panasonic E"
  rect 4x1.6 smd: 1(-3.1,0) 2(3.1,0)
  silkscreen extent -4.25,-4.25 4.25,4.25, body extent -4.25,-4.25 4.25,4.25, height 6.5
SM_RADIAL_G [mm] "10 x 10.2mm:  Panasonic G"
  rect 4.1x2 smd: 1(-4.35,0) 2(4.35,0)
  silkscreen extent -5.35,-5.35 5.35,5.35, body extent -5.25,-5.25 5.25,5.25, height 10.5
SMA [mm] "Molded Diode, 2-Leads, Body 4.3x2.6mm, IPC Medium Density, based on OnSemi component dimensions and land pattern"
  rect 2x2 smd: 1(-2,0) 2(2,0)
  silkscreen extent -3.66,-1.57 2.79,1.57, body extent -2.6,-1.3 2.6,1.3, height 2.42
SMB [mil] "Molded Diode, 2-Leads, Body 5.4x3.6mm, IPC Medium Density, based on OnSemi component dimensions"
  rect 85x107.99 smd: 1(-87.01,0) 2(87.01,0)
  silkscreen extent -155,-82 125,82, body extent -106,-71 106,71, height 91
SOD-123 [mm] "On Semi recommended land pattern"
  rect 0.915x1.22 smd: 1(-1.637,0) 2(1.637,0)
  silkscreen extent -2.74,-1.17 2.03,1.17, body extent -1.93,-0.9 1.93,0.9, height 1.35
SOD-323F [mm] "NXP recommended land pattern"
  rect 0.6x0.6 smd paste-0.05: 1(-1.1,0) 2(1.1,0)
  silkscreen extent -2.06,-0.86 1.53,0.86, body extent -1.35,-0.67 1.35,0.68, height 0.79
SOT-23 [mm] "SOT23, 3-Leads, Body 2.9x1.3mm, Pitch 0.95mm, Lead Span 2.5mm, IPC Medium Density"
  rrect50% 1x0.6 smd: 1(-1.2,0.95) 2(-1.2,-0.95) 3(1.2,0)
  silkscreen extent -1.63,-1.5 0.7,1.5, body extent -1.16,-1.45 1.21,1.45, height 1
SOT-89-3 [mm] "SOT, 3-Leads, Body 4.6 x 2.6 mm, Pitch 1.5mm"
  rect 1.4x0.9 smd: 1(-1.9,1.5) 3(-1.9,-1.5)
  rect 1.8x0.9 smd: 2(-1.7,0)
  oct 3.4x1.9 smd: 4(0.9,0)
  silkscreen extent -1.3,-2.45 1.33,2.45, body extent -2.42,-2.28 1.83,2.32, height 1.62
TEC_1-406541-1 [mm] "TE Connectivity"
  round 1.4 hole 0.89: 1(3.56,-0.18) 2(2.54,1.6) 3(1.52,-0.18) 4(0.5,1.6) 5(-0.52,-0.18) 6(-1.54,1.6) 7(-2.56,-0.18) 8(-3.58,1.6)
  round 2.1 hole 1.57: 9(8.12,0.71) 10(-8.14,0.71)
  round 3.759 hole 3.251: 11(6.34,-2.72) 12(-6.36,-2.72)
  silkscreen extent -9.69,-8 9.69,8.06, body extent -9.33,-8 9.31,7.75, height 14.8
TERM_BLK_ED555-2DS [mil]
  rrect4% 100x100 hole 50: 1(0,0)
  round 100 hole 50: 2(138,0)
  silkscreen extent -93,-161 215,113, body extent -69,-150 207,106, height 323
TRANS_Fairchild_PQFN08A [mm] "Fairchild PQFN08A recommended land pattern"
  rect 1.27x0.61 smd: 1(-2.67,1.905) 2(-2.67,0.635) 3(-2.67,-0.635) 4(-2.67,-1.905) 5(2.67,-1.905) 6(2.67,-0.635) 7(2.67,0.635) 8(2.67,1.905)
  Top Layer region: -1.215,-2.55 2.535,-2.55 2.535,2.55 -1.215,2.55
  silkscreen extent -3.2,-2.7 3.2,2.7, body extent -3.05,-2.55 3.05,2.55, height 1.11
Wurth_7490220122 [mm] "SMD, 24-Leads, Body 14.7x18.29mm"
  rect 2.29x0.76 smd: 1(-7.24,6.985) 2(-7.24,5.715) 3(-7.24,4.445) 4(-7.24,3.175) 5(-7.24,1.905) 6(-7.24,0.635) 7(-7.24,-0.635) 8(-7.24,-1.905) 9(-7.24,-3.175) 10(-7.24,-4.445) 11(-7.24,-5.715) 12(-7.24,-6.985) 13(7.24,-6.985) 14(7.24,-5.715) 15(7.24,-4.445) 16(7.24,-3.175) 17(7.24,-1.905) 18(7.24,-0.635) 19(7.24,0.635) 20(7.24,1.905) 21(7.24,3.175) 22(7.24,4.445) 23(7.24,5.715) 24(7.24,6.985)
  silkscreen extent -7.7,-9.15 7.35,9.15, body extent -7.35,-9.15 7.35,9.15, height 8.81
XAL5030 [mil] "Coilcraft XAL5030 12/12/11"
  rect 46x183 smd: 1(-65,0) 2(65,0)
  silkscreen extent -108,-112 108,112, body extent -108,-112 108,112, height 122

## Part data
C1 C2 C13 C14 C33 C34: library part CMP-0007053-4, "CAP, CERM, 1000 pF, 100 V, +/- 10%, X7R, 0603", Cap_Case=0603, Manufacturer=TDK, PartNumber=C1608X7R2A102K080AA, Supplier Part Number 1=445-1298-1-ND, TempCo=X7R, Tolerance_%=10%, Value1=Unknown, Value2=100V, ValueDisplayed=1000pF
C3 C4 C5 C6 C15 C16 C17 C18: library part CMP-0007209-4, "CAP, CERM, 330 pF, 50 V, +/- 5%, C0G/NP0, 0603", Cap_Case=0603, Manufacturer=MuRata, PartNumber=GRM1885C1H331JA01D, Supplier Part Number 1=490-1439-1-ND, TempCo=C0G/NP0, Tolerance_%=5%, Value1=Unknown, Value2=50V, ValueDisplayed=330pF
C7 C12 C19 C24: library part CMP-0009438-2, "CAP, CERM, 1000 pF, 2000 V, +/- 10%, X7R, 1812", Cap_Case=1812, Manufacturer=MuRata, PartNumber=GR443QR73D102KW01L, TempCo=X7R, Tolerance_%=10%, Value1=Unknown, Value2=2000V, ValueDisplayed=1000pF
C8 C9 C10 C11 C20 C21 C22 C23: library part CMP-0007468-5, "CAP, CERM, 0.01 uF, 100 V, +/- 10%, X7R, 0603", Cap_Case=0603, Manufacturer=MuRata, PartNumber=GRM188R72A103KA01D, Supplier Part Number 1=GRM188R72A103KA01D-ND, TempCo=X7R, Tolerance_%=10%, Value1=Unknown, Value2=100V, ValueDisplayed=0.01uF
C25 C26 C35 C36 C70: library part CMP-0011200-2, "CAP, AL, 47 uF, 80 V, +/- 20%, 0.7 ohm, AEC-Q200 Grade 2, SMD", Cap_Case=G, Manufacturer=Panasonic, PartNumber=EEE-FK1K470P, Supplier Part Number 1=PCE3831CT-ND, Tolerance_%=20%, Value1="0.7 ohm", Value2=80V, ValueDisplayed=47uF
C27 C32 C37 C42 C51 C52: library part CMP-0007886-2, "CAP, CERM, 0.1 uF, 100 V, +/- 10%, X7R, 0805", Cap_Case=0805, Manufacturer=TDK, PartNumber=C2012X7R2A104K125AA, Supplier Part Number 1=445-1418-1-ND, TempCo=X7R, Tolerance_%=10%, Value1="0.020726 ohm", Value2=100V, ValueDisplayed=0.1uF
C28 C29 C38 C39 C65: library part CMP-0007432-5, "CAP, CERM, 1000 pF, 50 V, +/- 10%, X7R, 0603", Cap_Case=0603, Manufacturer=MuRata, PartNumber=GRM188R71H102KA01D, Supplier Part Number 1=490-1494-1-ND, TempCo=X7R, Tolerance_%=10%, Value1=Unknown, Value2=50V, ValueDisplayed=1000pF
C30 C40 C60 C61: library part CMP-0007043-4, "CAP, CERM, 0.01 uF, 50 V, +/- 10%, X7R, 0603", Cap_Case=0603, Manufacturer=TDK, PartNumber=C1608X7R1H103K080AA, Supplier Part Number 1=445-1311-1-ND, TempCo=X7R, Tolerance_%=10%, Value1="0.0539 ohm", Value2=50V, ValueDisplayed=0.01uF
C31: library part CMP-0011195-2, "CAP, AL, 10 uF, 80 V, +/- 20%, 2.4 ohm, AEC-Q200 Grade 2, SMD", Cap_Case=E, Manufacturer=Panasonic, PartNumber=EEE-FK1K100P, Supplier Part Number 1=PCE3826CT-ND, Tolerance_%=20%, Value1="2.4 ohm", Value2=80V, ValueDisplayed=10uF
C41 C57: library part CMP-0009358-2, "CAP, CERM, 2200 pF, 2000 V, +/- 10%, X7R, 1812", Cap_Case=1812, Manufacturer=TDK, PartNumber=C4532X7R3D222K130KA, Supplier Part Number 1=445-2389-1-ND, TempCo=X7R, Tolerance_%=10%, Value1=Unknown, Value2=2000V, ValueDisplayed=2200pF
C43 C44 C45: library part CMP-0009098-2, "CAP, CERM, 100 uF, 6.3 V, +/- 20%, X5R, 1210", Cap_Case=1210_280, Manufacturer=TDK, PartNumber=C3225X5R0J107M250AC, Supplier Part Number 1=445-1437-1-ND, TempCo=X5R, Tolerance_%=20%, Value1="0.005496 ohm", Value2=6.3V, ValueDisplayed=100uF
C46: library part CMP-0012153-3, "CAP, Aluminum Polymer, 330 uF, 6.3 V, +/- 20%, 0.025 ohm, 10x10.3 SMD", Cap_Case=10.3x10.3x7.9, Manufacturer=Panasonic, PartNumber=6SVP330M, Tolerance_%=20%, Value1="0.025 ohm", Value2=6.3V, ValueDisplayed=330uF
C47 C48 C49 C100 C101: library part CMP-0009232-2, "CAP, CERM, 2.2 uF, 100 V, +/- 10%, X7R, 1210", Cap_Case=1210, Manufacturer=MuRata, PartNumber=GRM32ER72A225KA35L, Supplier Part Number 1=490-3385-1-ND, TempCo=X7R, Tolerance_%=10%, Value1="0.007 ohm", Value2=100V, ValueDisplayed=2.2uF
C50 C53 C59 C67: library part CMP-0008336-2, "CAP, CERM, 1 uF, 25 V, +/- 10%, X7R, 0805", Cap_Case=0805, Manufacturer=MuRata, PartNumber=GRM21BR71E105KA99L, Supplier Part Number 1=GRM21BR71E105KA99L-ND, TempCo=X7R, Tolerance_%=10%, Value1=Unknown, Value2=25V, ValueDisplayed=1uF
C54: library part CMP-0008690-2, "CAP, CERM, 10 uF, 16 V, +/- 10%, X7R, 1206_190", Cap_Case=1206, Manufacturer=TDK, PartNumber=C3216X7R1C106K160AC, Supplier Part Number 1=445-4042-1-ND, TempCo=X7R, Tolerance_%=10%, Value1=Unknown, Value2=16V, ValueDisplayed=10uF
C55: library part CMP-0007221-4, "CAP, CERM, 470 pF, 50 V, +/- 5%, C0G/NP0, 0603", Cap_Case=0603, Manufacturer=MuRata, PartNumber=GRM1885C1H471JA01D, Supplier Part Number 1=490-1443-1-ND, TempCo=C0G/NP0, Tolerance_%=5%, Value1=Unknown, Value2=50V, ValueDisplayed=470pF
C56: library part CMP-0007456-4, "CAP, CERM, 4700 pF, 50 V, +/- 10%, X7R, 0603", Cap_Case=0603, Manufacturer=MuRata, PartNumber=GRM188R71H472KA01D, Supplier Part Number 1=490-1506-1-ND, TempCo=X7R, Tolerance_%=10%, Value1=Unknown, Value2=50V, ValueDisplayed=4700pF
C58: library part CMP-0007039-5, "CAP, CERM, 0.1 uF, 25 V, +/- 10%, X7R, 0603", Cap_Case=0603, Manufacturer=TDK, Supplier Part Number 1=445-1316-1-ND, TempCo=X7R, Tolerance_%=10%, Value1=Unknown, Value2=25V, ValueDisplayed=0.1uF
C62: library part CMP-0007049-4, "CAP, CERM, 0.047 uF, 50 V, +/- 10%, X7R, 0603", Cap_Case=0603, Manufacturer=TDK, PartNumber=C1608X7R1H473K080AA, Supplier Part Number 1=445-1313-1-ND, TempCo=X7R, Tolerance_%=10%, Value1="0.049007 ohm", Value2=50V, ValueDisplayed=0.047uF
C63: library part CMP-0008236-2, "CAP, CERM, 100 pF, 250 V, +/- 5%, C0G/NP0, 0805", Cap_Case=0805, Manufacturer=MuRata, PartNumber=GRM21A5C2E101JW01D, Supplier Part Number 1=490-5542-1-ND, TempCo=C0G/NP0, Tolerance_%=5%, Value1=Unknown, Value2=250V, ValueDisplayed=100pF
C64: library part CMP-0007171-4, "CAP, CERM, 100 pF, 50 V, +/- 5%, C0G/NP0, 0603", Cap_Case=0603, Manufacturer=MuRata, PartNumber=GRM1885C1H101JA01D, Supplier Part Number 1=490-1427-1-ND, TempCo=C0G/NP0, Tolerance_%=5%, Value1=Unknown, Value2=50V, ValueDisplayed=100pF
C66: library part CMP-0007428-4, "CAP, CERM, 0.068 uF, 25 V, +/- 10%, X7R, 0603", Cap_Case=0603, Manufacturer=MuRata, PartNumber=GRM188R71E683KA01D, Supplier Part Number 1=490-1523-1-ND, TempCo=X7R, Tolerance_%=10%, Value1=Unknown, Value2=25V, ValueDisplayed=0.068uF
C68 C69: library part CMP-0007887-2, "CAP, CERM, 0.047 uF, 100 V, +/- 10%, X7R, 0805", Cap_Case=0805, Manufacturer=TDK, PartNumber=C2012X7R2A473K125AA, Supplier Part Number 1=445-2276-1-ND, TempCo=X7R, Tolerance_%=10%, Value1="0.049089 ohm", Value2=100V, ValueDisplayed=0.047uF
D1 D2 D3 D4 D5 D6 D7 D8 D16 D18 D26 D35 D36 D37 D38 D39 D40 D41 D42: library part CMP-0028397-1, "Diode, Schottky, 100 V, 2 A, SMB", Manufacturer="Diodes Inc.", Supplier Part Number 1=B2100-FDICT-ND, Value1=2A, Value2=0.79V
D9 D10 D19 D20: library part CMP-0076982-1, "Diode, Switching, 75 V, 0.3 A, SOD-523F", Manufacturer="Fairchild Semiconductor", Supplier Part Number 1=1N4148WTCT-ND, Value1=0.3A, Value2=V
D11 D13 D21 D34: library part CMP-0005485-2, "Diode, TVS, Uni, 58 V, SMA", Manufacturer="Diodes Inc.", Power_W=1W, Supplier Part Number 1=SMAJ58A-13-FDICT-ND
D12: library part CMP-0005999-1, "Diode, Zener, 5.1 V, 225 mW, SOT-23", Manufacturer="ON Semiconductor", Power_W=225mW, Supplier Part Number 1=MMBZ5231BLT1GOSCT-ND, Value1=0.225W
D14 D22: library part CMP-0076946-1, "Diode, Schottky, 100 V, 0.25 A, SOD-323F", Manufacturer=Nexperia, Supplier Part Number 1=568-6017-1-ND, Value1=0.25A, Value2=0.85V
D15 D17 D23 D25: library part CMP-0005949-1, "Diode, Zener, 10 V, 225 mW, SOT-23", Manufacturer="ON Semiconductor", Power_W=225mW, Supplier Part Number 1=MMBZ5240BLT1GOSCT-ND, Value1=0.225W
D24: library part CMP-0005802-1, "Diode, Zener, 5.1 V, 500 mW, SOD-123", Manufacturer="Diodes Inc.", Power_W=500mW, Supplier Part Number 1=MMSZ5231B-FDICT-ND, Value1=0.5W
D27: library part CMP-0028353-1, "Diode, Schottky, 40 V, 3 A, SMA", Manufacturer="Diodes Inc.", Supplier Part Number 1=B340A-FDICT-ND, Value1=3A, Value2=0.5V
D28: library part CMP-0076890-1, "Diode, Ultrafast, 200 V, 2 A, SMB", Manufacturer="Diodes Inc.", Supplier Part Number 1=ES2D-FDICT-ND, Value1=2A, Value2=0.92V
D29 D30 D31 D32: library part CMP-0029032-1, "Diode, Switching, 100 V, 0.2 A, SOD-123", Manufacturer="ON Semiconductor", Supplier Part Number 1=MMSD4148T1GOSCT-ND, Value1=0.2A, Value2=1V
D33: library part CMP-0028456-1, "Diode, Schottky, 30 V, 0.2 A, SOT-23", Manufacturer="Diodes Inc.", Supplier Part Number 1=BAT54S-FDICT-ND, Value1=0.2A, Value2=0.65V
D43: library part CMP-0005528-4, "Diode, Zener, 24 V, 1 W, SMA", Manufacturer="Diodes Inc.", Power_W=1W
J1 J2 J3 J4: library part CMP-0054918-1, "RJ45, No LED, tab up, R/A, TH", Color=Black, Manufacturer="TE Connectivity", Supplier Part Number 1=A97716-ND
J5 J6 J9 J10: library part CMP-0002337-1, "Header, 100mil, 2x1, Tin, TH", Color=Black, Current_A=3A, Manufacturer="Sullins Connector Solutions", Supplier Part Number 1=S1012E-02-ND, Voltage_V=1.8kV
J7 J8: library part CMP-0074913-1, "Terminal Block, 3.5mm Pitch, 2x1, TH", Color=Grey, Current_A=6A, Manufacturer="On-Shore Technology", Supplier Part Number 1=ED1514-ND, Voltage_V=150V
L1 L2 L3 L4 L5 L6: library part CMP-0003425-2, "Ferrite Bead, 220 ohm @ 100 MHz, 2.2 A, 0603", Manufacturer=TDK, PartNumber=MPZ1608S221A, Supplier Part Number 1=445-1565-1-ND, Value1="0.05 ohm", Value2=2.2A, ValueDisplayed="220 ohm"
L7: library part CMP-0061002-1, "Inductor, Shielded, Composite, 330 nH, 19.2 A, 0.0032 ohm, SMD", Manufacturer=Coilcraft, Value1="0.0032 ohm", Value2=19.2A, ValueDisplayed=330nH
L8: library part CMP-0060473-1, "Inductor, Shielded Drum Core, Ferrite, 3.3 uH, 1.9 A, 0.08 ohm, SMD", Manufacturer=Coilcraft, Value1="0.08 ohm", Value2=1.9A, ValueDisplayed=3.3uH
Q1 Q2 Q3 Q4 Q20 Q21 Q22 Q23: library part CMP-0000969-2, "MOSFET, N-CH, 100 V, 5 A, DNH0008A (VSONP-8)", Alternate Manufacturer=None, Manufacturer="Texas Instruments", Value2="7.2 nC"
Q5 Q6 Q7 Q13: library part CMP-0000366-2, "Transistor, PNP, 100 V, 0.2 A, SOT-23", Manufacturer="Fairchild Semiconductor", Supplier Part Number 1=BSS63CT-ND, Value1="0.2 A"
